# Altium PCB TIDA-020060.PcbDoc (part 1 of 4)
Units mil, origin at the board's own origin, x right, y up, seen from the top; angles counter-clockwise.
Board outline 2114.94 x 3612.21 mil, 4 copper layers (Top Layer, Signal Layer 1, Signal Layer 2, Bottom Layer), stack 61.811 mil thick; 272 components, 167 nets, 840 pads, 352 vias.
Unrouted connection lines stored in the file: 261.
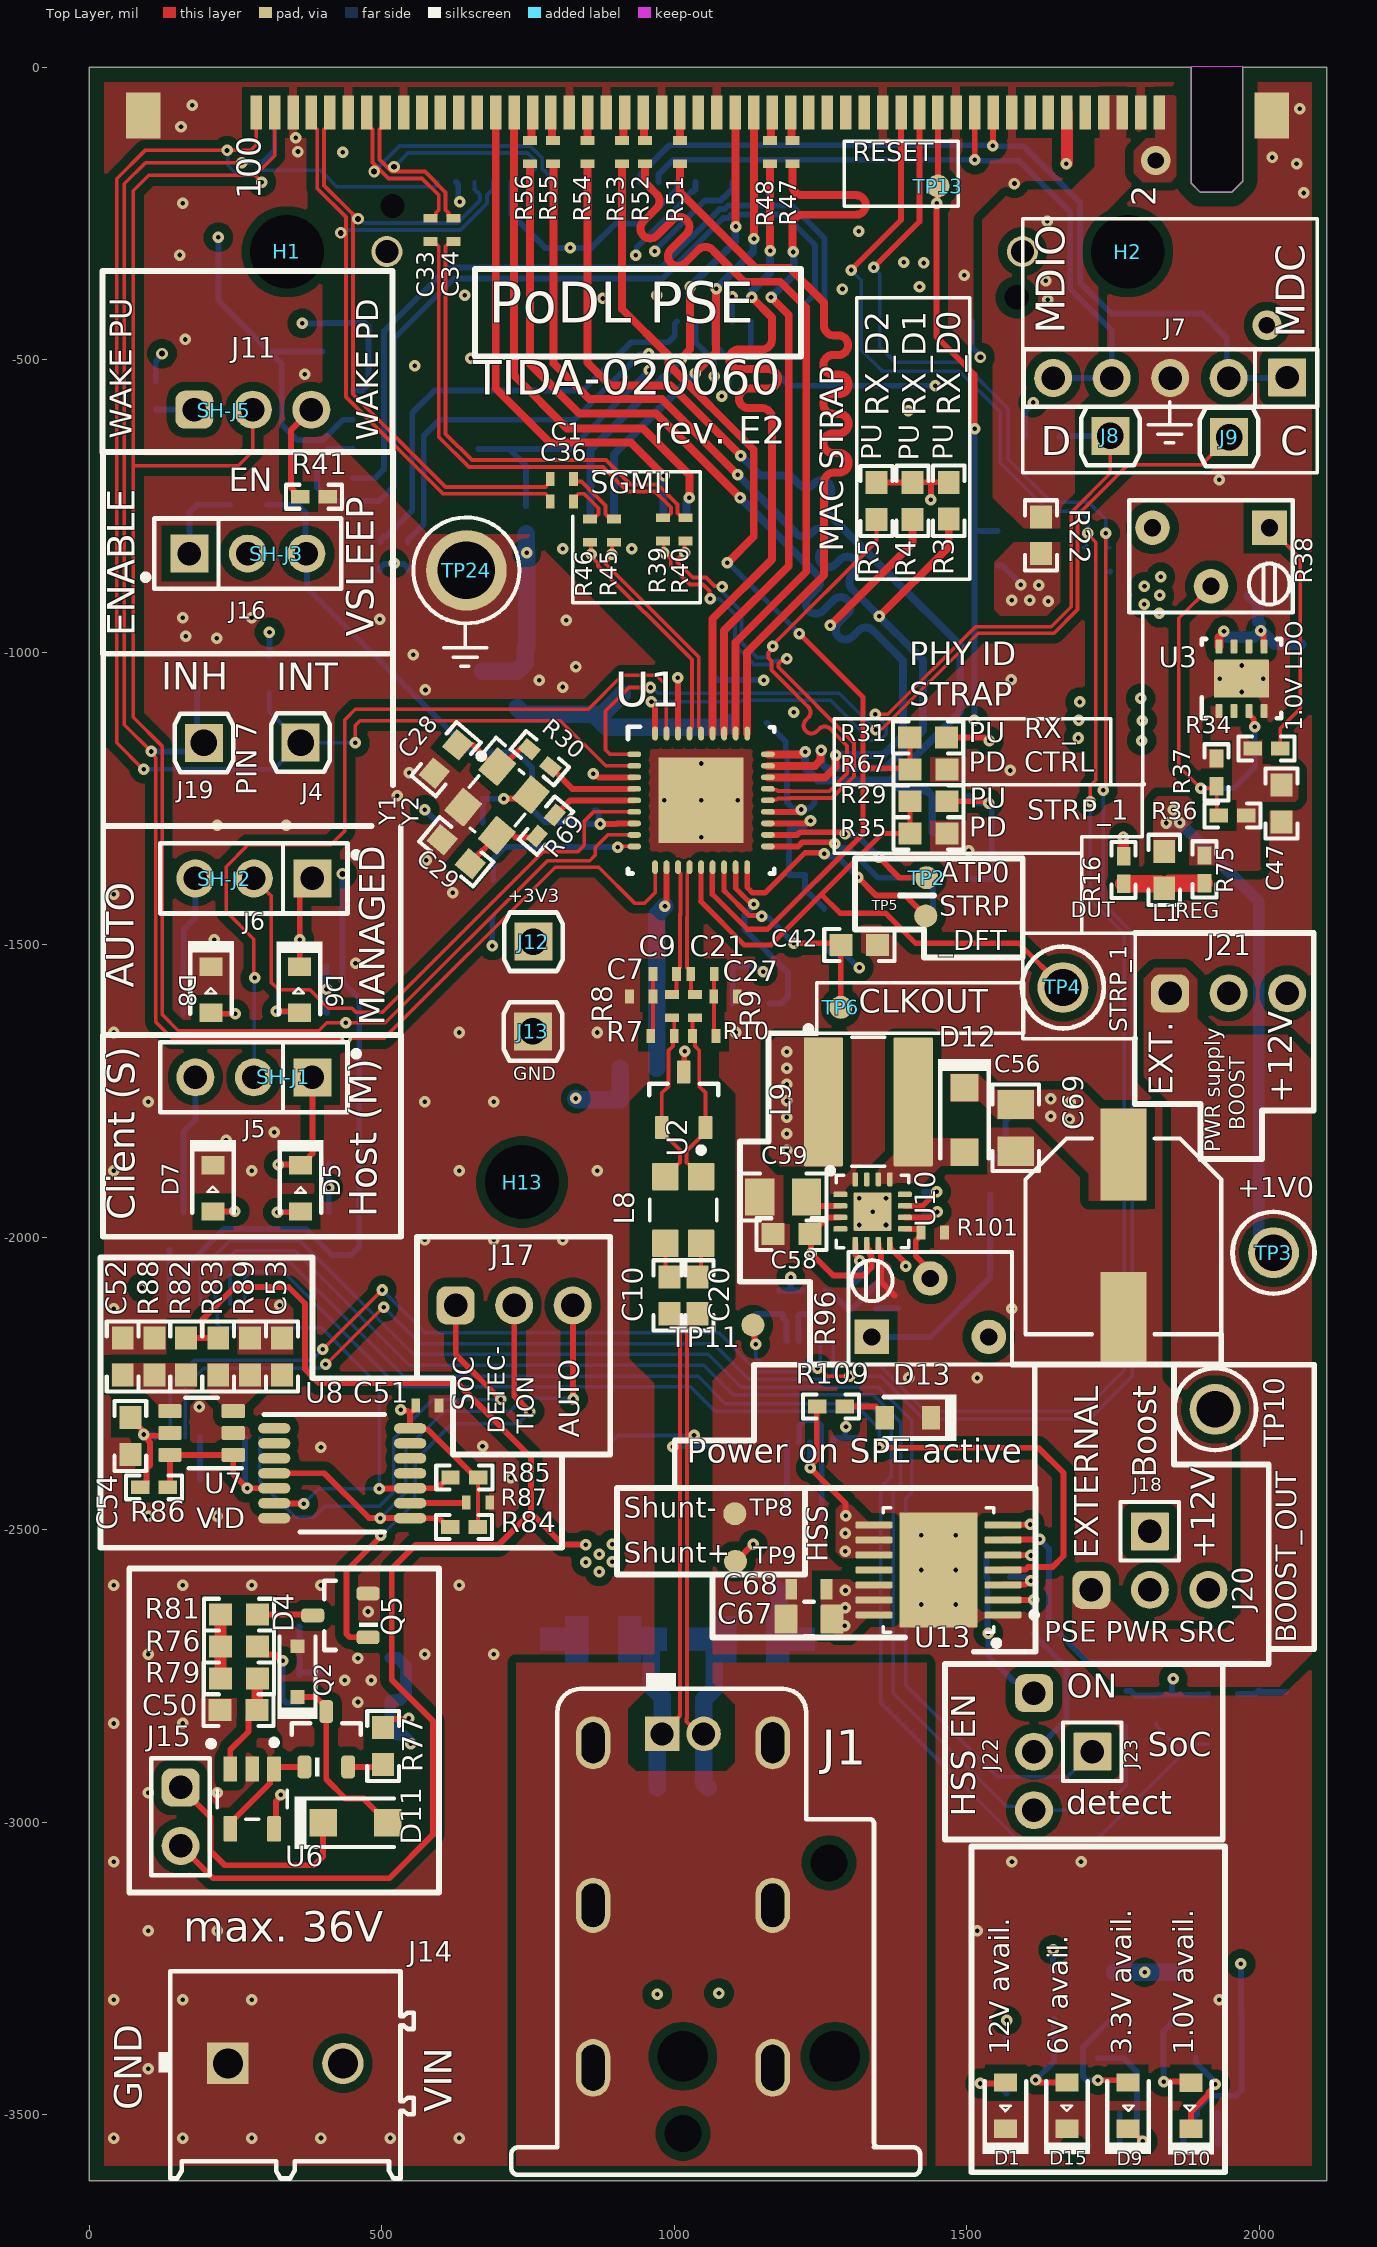
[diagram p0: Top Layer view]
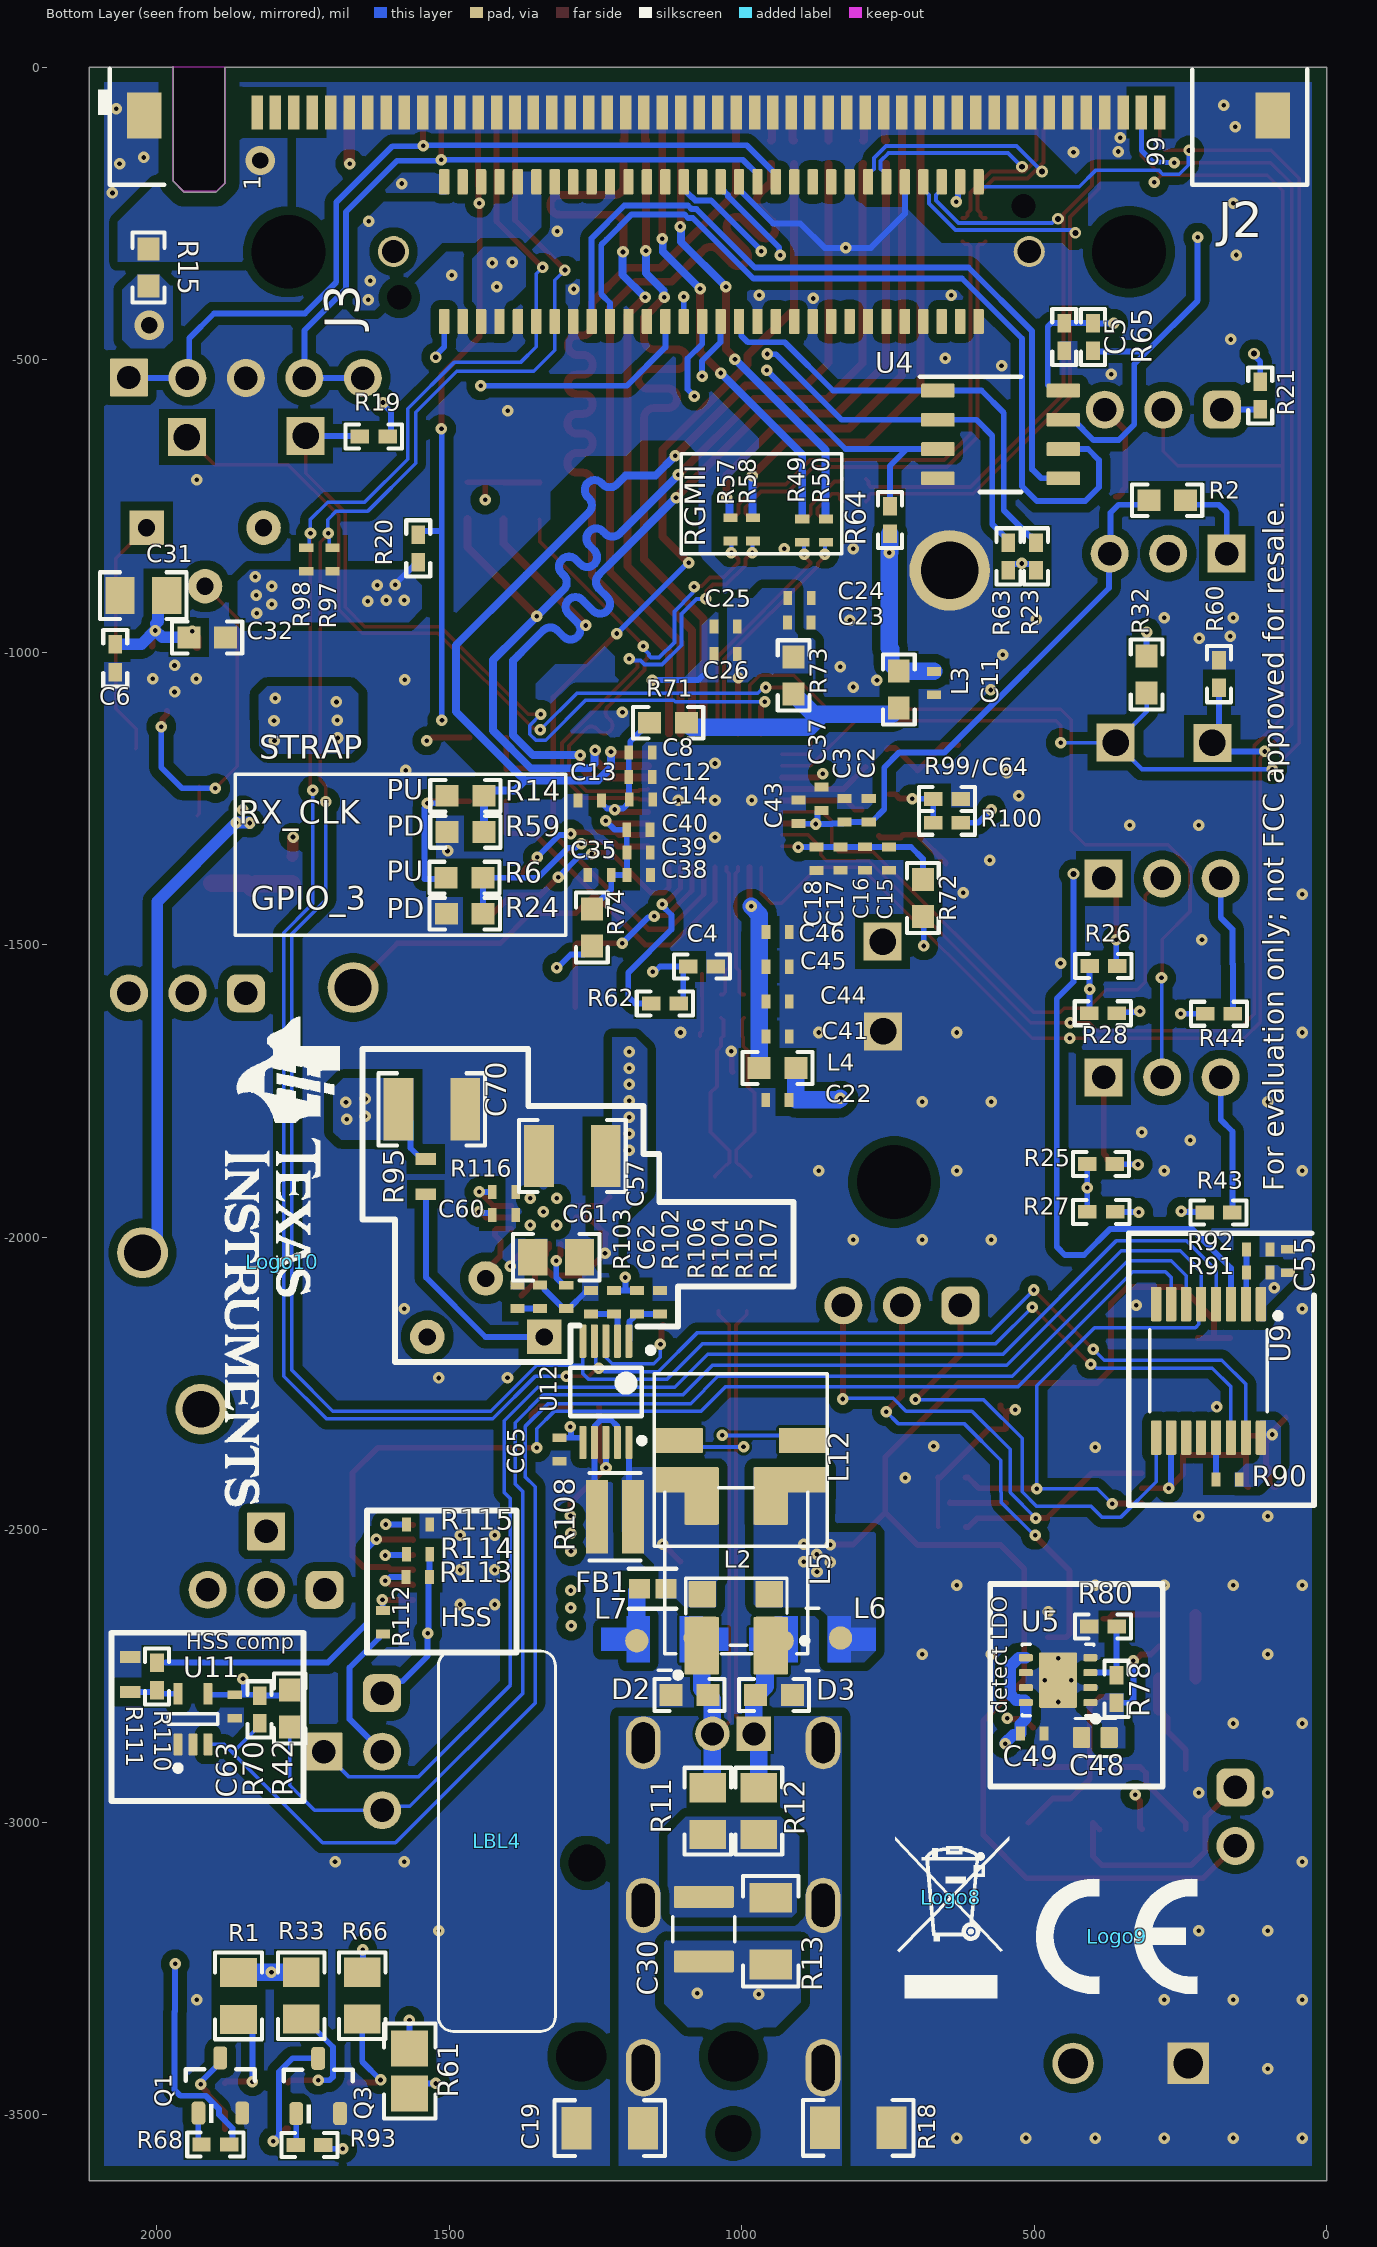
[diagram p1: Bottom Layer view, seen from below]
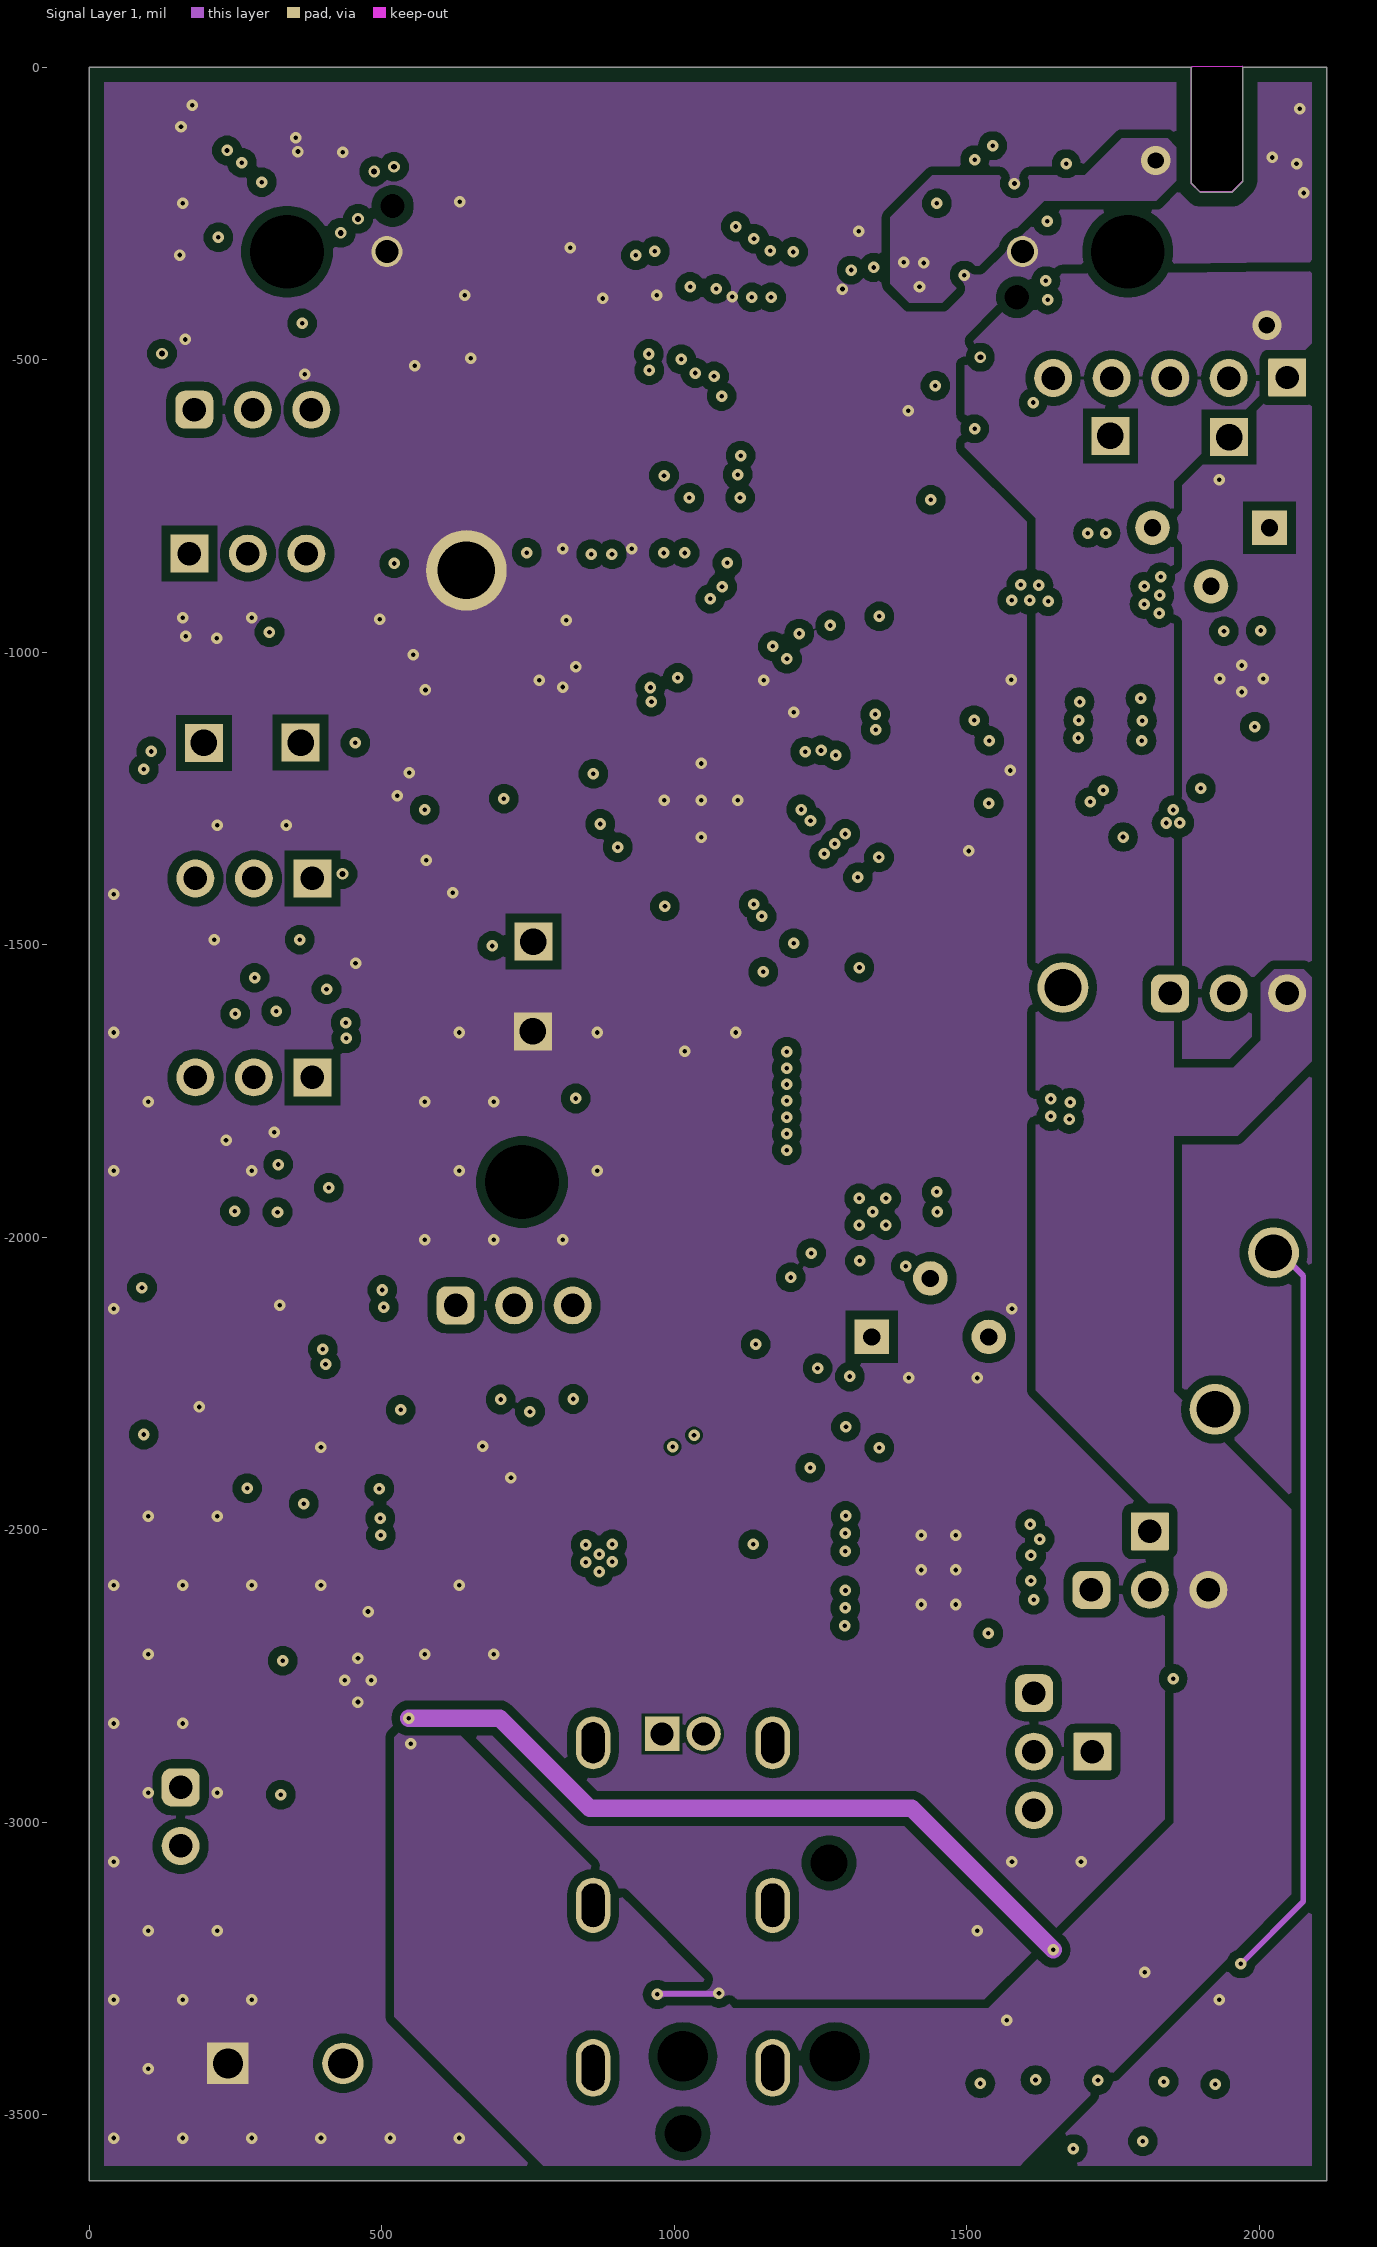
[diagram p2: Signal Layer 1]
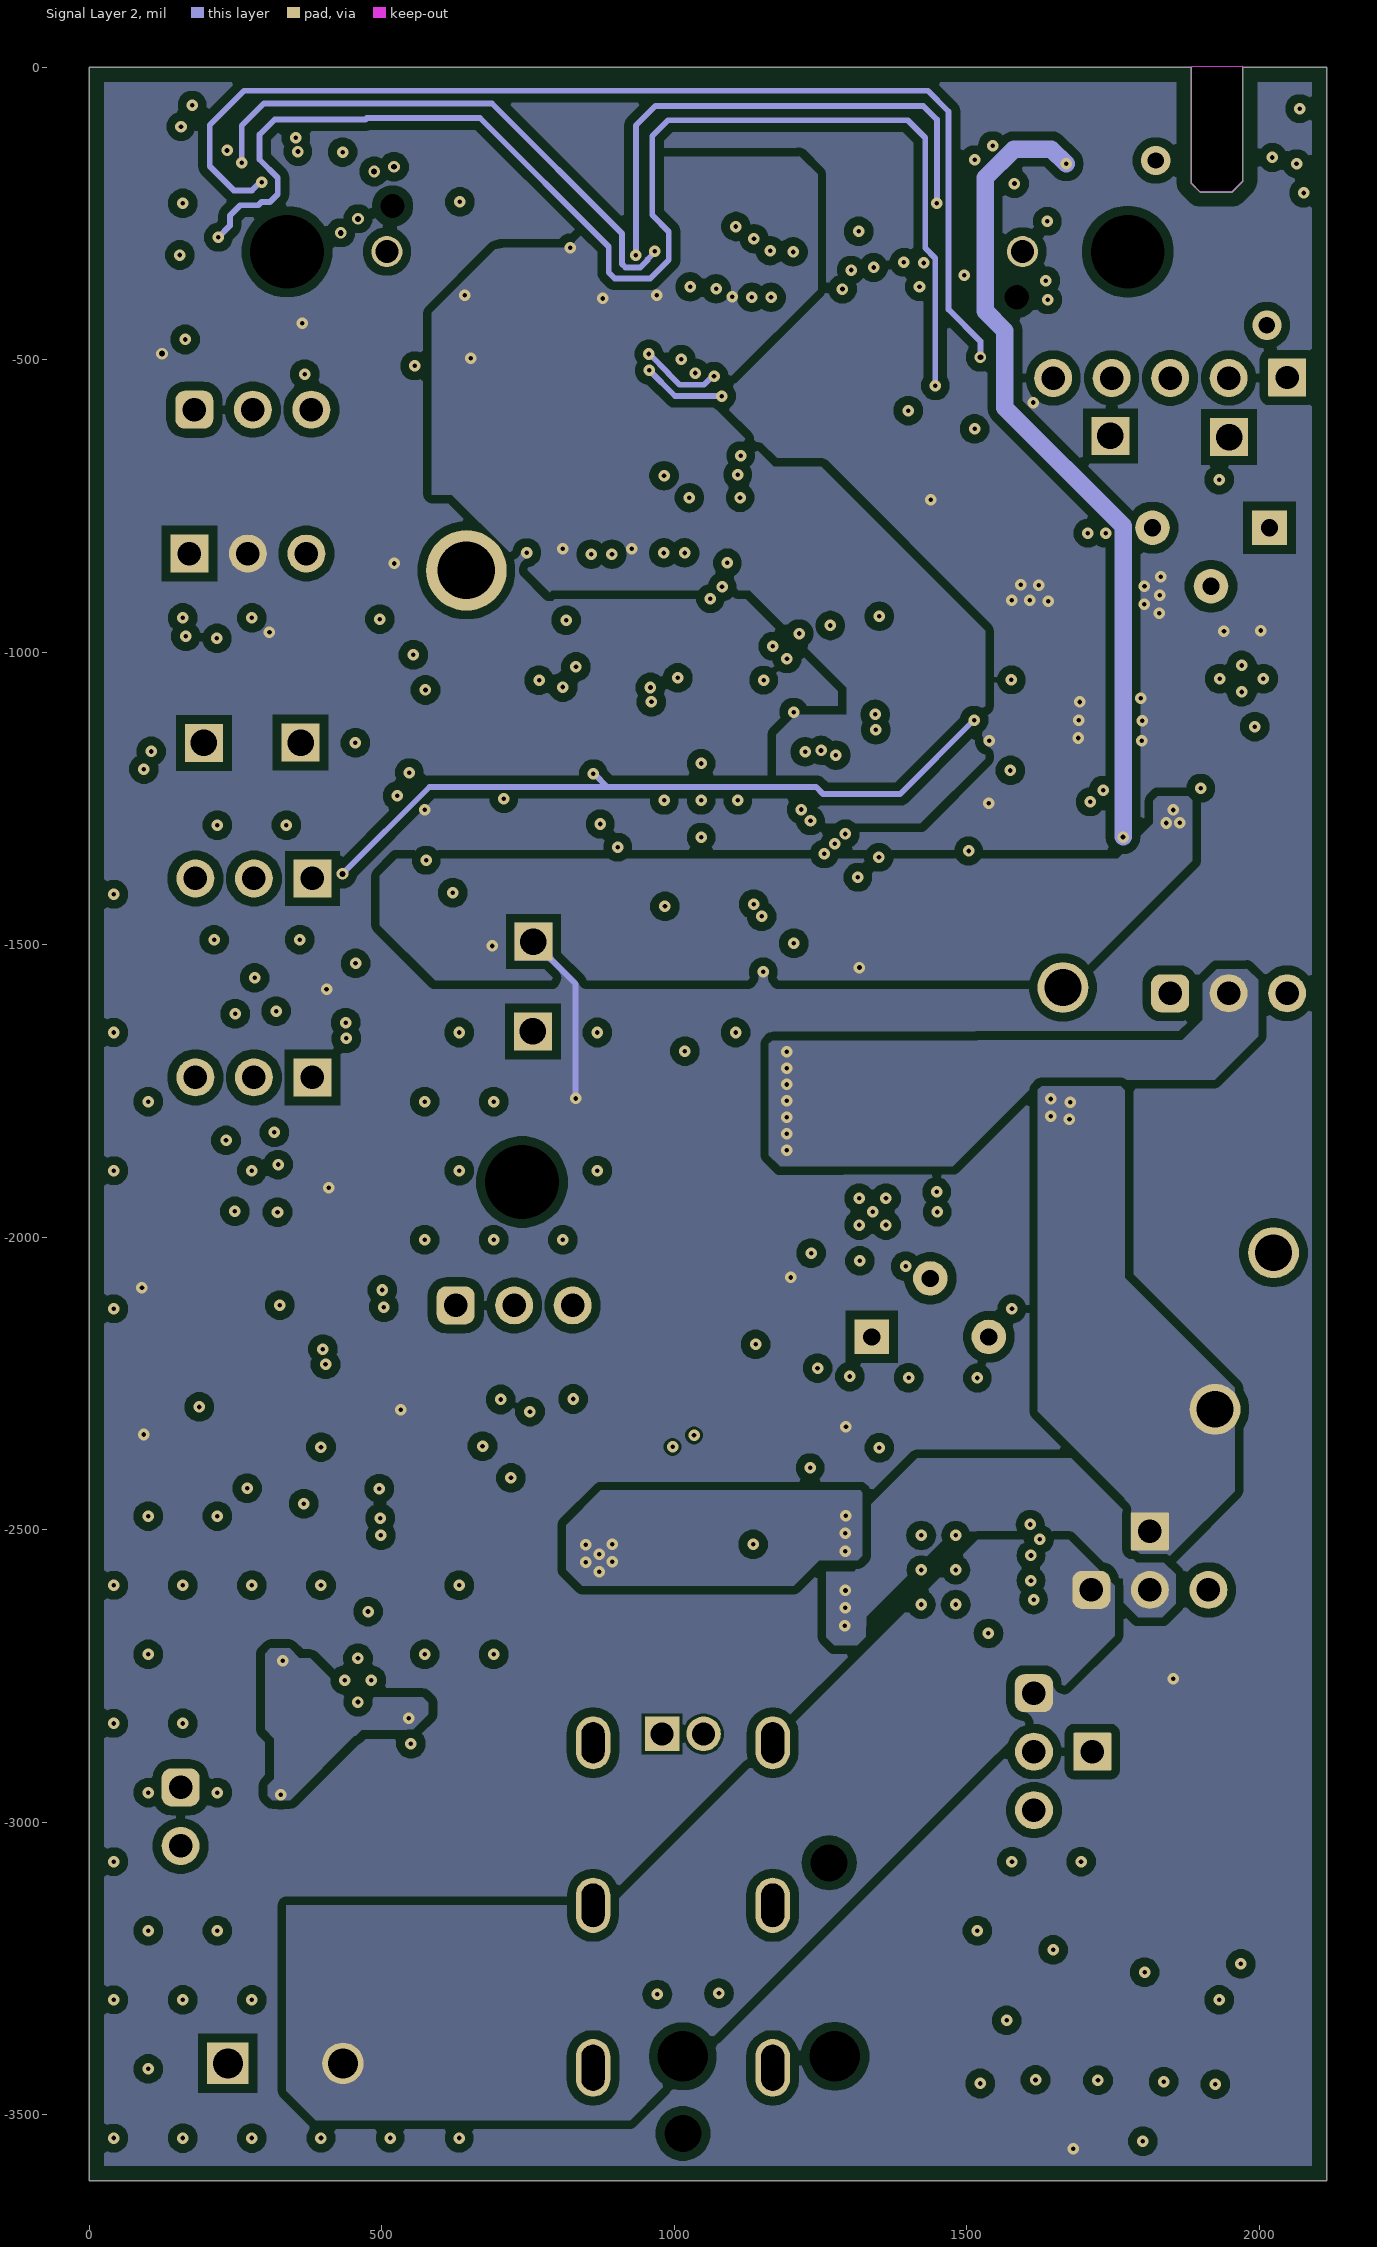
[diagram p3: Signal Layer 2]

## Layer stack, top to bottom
Top Solder: solder mask 0.4, Solder Resist, Dk 3.5
Top Layer: signal copper 1.378
Dielectric1: prepreg 7.874, PP-022, Dk 4.5
Signal Layer 1: signal copper 1.378
Dielectric 2: core 40.5512, Core-042, Dk 4.6
Signal Layer 2: signal copper 1.378
Dielectric 3: prepreg 7.874, PP-022, Dk 4.5
Bottom Layer: signal copper 1.378
Bottom Solder: solder mask 0.4, Solder Resist, Dk 3.5

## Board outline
0,-3612.21 2114.94,-3612.21 2114.94,0 1971.39,0 1971.39,-195 1953.39,-213 1898.64,-213 1883.39,-197.75 1883.39,0 0,0
cut-out: 1884.39,0 1883.39,-1 1883.39,-197.75 1898.64,-213 1953.39,-213 1971.39,-195 1971.39,1

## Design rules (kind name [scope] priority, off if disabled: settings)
AcuteAngle [All] p1: minimum=4.50000000000000E+0001 checktracksonly=FALSE
AssemblyTestPointUsage [All] p1: valid=2
BoardOutlineClearance BoardOutlineClearance_MountingHoles [OnCopper and InComponentClass('Mounting Holes')] p1: gap=35 ignorepadtopadclearanceinfootprint=FALSE
BoardOutlineClearance BoardOutlineClearance_Poly [OnCopper and IsPoly] p2: gap=25 ignorepadtopadclearanceinfootprint=FALSE
BoardOutlineClearance [OnCopper and Not InComponentClass('Logo') and not InComponentClass('FiducialMark') and not InRegion(1000,500,4000,800) and not InPoly] p3: gap=35 ignorepadtopadclearanceinfootprint=FALSE
Clearance Clearance_Keepouts_FID [IsKeepOut and InComponentClass('FiducialMark') vs IsPad and InComponentClass('FiducialMark')] p1: gap=0 ignorepadtopadclearanceinfootprint=FALSE
Clearance Clearance_Keepouts [((IsTrack Or IsArc) And Not InPoly) And IsFree and IsKeepOut vs ((IsTrack Or IsArc) And Not InPoly) And IsFree and IsKeepOut] p2: gap=0 ignorepadtopadclearanceinfootprint=FALSE
Clearance Clearance_Poly_Connectors [InRegionRelative(3345,2820,4790,2995) or InRegionRelative(4870,2815,6285,2995) or InRegionRelative(6370,2790,7785,2995)] p3: gap=5 ignorepadtopadclearanceinfootprint=TRUE except(0: Arc-Hole Track-Hole SMDPad-Hole THPad-Hole Via-Hole Fill-Hole Poly-Hole Region-Hole Text-Hole; 10: Arc-Fill Arc-Poly Arc-Region Track-Fill Track-Poly Track-Region SMDPad-Fill SMDPad-Poly SMDPad-Region THPad-Fill THPad-Poly THPad-Region Via-Fill Via-Poly Via-Region Fill-Fill Fill-Poly Fill-Region Poly-Poly Poly-Region Region-Region)
Clearance Clearance_Poly_100OHM [InNetClass('100 OHM')] p4: gap=5 ignorepadtopadclearanceinfootprint=TRUE except(0: Arc-Hole Track-Hole SMDPad-Hole THPad-Hole Via-Hole Fill-Hole Poly-Hole Region-Hole Text-Hole)
Clearance "Clearance_Poly_50OHM_Outer Layers" [InNetClass('50 Ohm') vs OnLayer('Top Layer') or OnBottomLayer] p5: gap=5 ignorepadtopadclearanceinfootprint=TRUE except(0: Arc-Hole Track-Hole SMDPad-Hole THPad-Hole Via-Hole Fill-Hole Poly-Hole Region-Hole Text-Hole; 15: Fill-Fill Fill-Poly Fill-Region Poly-Poly Poly-Region Region-Region; 27: Arc-Fill Arc-Poly Arc-Region Track-Fill Track-Poly Track-Region SMDPad-Fill SMDPad-Poly SMDPad-Region THPad-Fill THPad-Poly THPad-Region Via-Fill Via-Poly Via-Region)
Clearance "Clearance_Poly_50OHM_Inner Layers" [InNetClass('50 Ohm')] p6: gap=5 ignorepadtopadclearanceinfootprint=FALSE except(0: Arc-Hole Track-Hole SMDPad-Hole THPad-Hole Via-Hole Fill-Hole Poly-Hole Region-Hole Text-Hole; 15: Fill-Fill Fill-Poly Fill-Region Poly-Poly Poly-Region Region-Region; 22.5: Arc-Fill Arc-Poly Arc-Region Track-Fill Track-Poly Track-Region SMDPad-Fill SMDPad-Poly SMDPad-Region THPad-Fill THPad-Poly THPad-Region Via-Fill Via-Poly Via-Region)
Clearance Clearance_720Gnd [InNet('720_GND') vs InNet('NetC66_1')] p7: gap=15 ignorepadtopadclearanceinfootprint=FALSE except(0: Arc-Hole Track-Hole SMDPad-Hole THPad-Hole Via-Hole Fill-Hole Poly-Hole Region-Hole Text-Hole; 45: Fill-Fill Fill-Poly Fill-Region Poly-Poly Poly-Region Region-Region)
Clearance Clearance_867GND [InNet('867_GND') vs InNet('PHY1_EARTH')] p8: gap=15 ignorepadtopadclearanceinfootprint=FALSE except(0: Arc-Hole Track-Hole SMDPad-Hole THPad-Hole Via-Hole Fill-Hole Poly-Hole Region-Hole Text-Hole; 7.79: Arc-Arc Arc-Track Track-Track; 45: Fill-Fill Fill-Poly Fill-Region Poly-Poly Poly-Region Region-Region)
Clearance Clearance_822GND [InNet('822_GND') vs InNet('ETH1_EARTH')] p9: gap=15 ignorepadtopadclearanceinfootprint=FALSE except(0: Arc-Hole Track-Hole SMDPad-Hole THPad-Hole Via-Hole Fill-Hole Poly-Hole Region-Hole Text-Hole; 45: Fill-Fill Fill-Poly Fill-Region Poly-Poly Poly-Region Region-Region)
Clearance Clearance_Poly [InPolygon] p10: gap=15 ignorepadtopadclearanceinfootprint=FALSE except(0: Arc-Hole Track-Hole SMDPad-Hole THPad-Hole Via-Hole Fill-Hole Poly-Hole Region-Hole Text-Hole)
Clearance Clearance_FiducialMark [IsKeepOut and InComponentClass('FiducialMark') vs IsPad and InComponentClass('FiducialMark')] p11: gap=0 ignorepadtopadclearanceinfootprint=FALSE
Clearance Clearance_Keepouts_J6 [IsKeepOut and InComponent('J6') vs IsPad and InComponent('J6')] p12: gap=0 ignorepadtopadclearanceinfootprint=FALSE
Clearance [All] p13: gap=5 ignorepadtopadclearanceinfootprint=TRUE except(0: Arc-Hole Track-Hole SMDPad-Hole THPad-Hole Via-Hole Fill-Hole Poly-Hole Region-Hole Text-Hole)
ComponentClearance ComponentClearance_MountingHoles_FiducialMarks [InComponentClass('Mounting Holes') vs InComponentClass('FiducialMark')] p1: gap=20 collisioncheckmode=3 verticalgap=10 showdistances=FALSE
ComponentClearance ComponentClearance_Shunt [InComponentClass('Header') vs InComponentClass('Shunt')] p2: gap=0 collisioncheckmode=3 verticalgap=0 showdistances=FALSE
ComponentClearance ComponentClearance_Logo [InComponentClass('Logo')] p3: gap=20 collisioncheckmode=3 verticalgap=10 showdistances=FALSE
ComponentClearance ComponentClearance_ScrewToNut [(HasFootprint('NY PMS 440 0025 PH')) vs (HasFootprint('Keystone_1902C'))] p4: gap=5 collisioncheckmode=3 verticalgap=10 showdistances=FALSE
ComponentClearance ComponentClearance_MountingHoles [InComponentClass('Mounting Holes')] p5: gap=70 collisioncheckmode=3 verticalgap=0 showdistances=FALSE
ComponentClearance ComponentClearance_SmallPassives [HasFootprint('0201*') or HasFootprint('0402*') or HasFootprint('0508') or HasFootprint('0603*') or HasFootprint('0612') or HasFootprint('0805*') or HasFootprint('0815*') or HasFootprint('0830*') or HasFootprint('1206*') or HasFootprint('1210*') or HasFootprint('1808*') or HasFootprint('1812*') or HasFootprint('1825*') or HasFootprint('2010*') or HasFootprint('2220*') or HasFootprint('2225*') or HasFootprint('2512*') or HasFootprint('2728*') or HasFootprint('3518*') vs HasFootprint('0201*') or HasFootprint('0402*') or HasFootprint('0508') or HasFootprint('0603*') or HasFootprint('0612') or HasFootprint('0805*') or HasFootprint('0815*') or HasFootprint('0830*') or HasFootprint('1206*') or HasFootprint('1210*') or HasFootprint('1808*') or HasFootprint('1812*') or HasFootprint('1825*') or HasFootprint('2010*') or HasFootprint('2220*') or HasFootprint('2225*') or HasFootprint('2512*') or HasFootprint('2728*') or HasFootprint('3518*')] p6: gap=15 collisioncheckmode=3 verticalgap=10 showdistances=FALSE
ComponentClearance ComponentClearance_THtoSMT [IsThruComponent vs IsSMTComponent] p7: gap=1 collisioncheckmode=3 verticalgap=1 showdistances=FALSE
ComponentClearance ComponentClearance_THtoTH [IsThruComponent vs IsThruComponent] p8: gap=20 collisioncheckmode=3 verticalgap=30 showdistances=FALSE
ComponentClearance [All] p9: gap=19.68 collisioncheckmode=3 verticalgap=10 showdistances=FALSE
DiffPairsRouting D100 [All] p1: maxlimit=5 minlimit=5 mostfreqgap=5 toplayer_minwidth=6.73 toplayer_maxwidth=6.73 toplayer_prefwidth=6.73 midlayer1_minwidth=2.59 midlayer1_maxwidth=2.59 midlayer1_prefwidth=2.59 midlayer4_minwidth=2.59 midlayer4_maxwidth=2.59 midlayer4_prefwidth=2.59 bottomlayer_minwidth=6.73 bottomlayer_maxwidth=6.73 bottomlayer_prefwidth=6.73 impedanceprofiledriven=TRUE maxuncoupledlength=500
FabricationTestPointUsage TestPointUsage [All] p1: valid=2 allowmultiple=FALSE
FabricationTestpoint Testpoint [All] p1: side=3 testpointundercomponent=TRUE minsize=40 maxsize=100 preferedsize=60 minholesize=0 maxholesize=40 preferedholesize=32 testpointgrid=1 allowsidetop=TRUE allowsidebottom=TRUE usegrid=TRUE gridtolerance=0.01
FanoutControl Fanout_LCC [IsLCC] p1: bgadir=Out bgaviamode=Centered fanoutstyle=Auto fanoutdirection=Alternating viagrid=1 // Fanout_LCC (Default Rule)
FanoutControl Fanout_BGA [IsBGA] p2: bgadir=Out bgaviamode=Centered fanoutstyle=Auto fanoutdirection=Alternating viagrid=1 // Fanout_BGA (Default Rule)
FanoutControl Fanout_Default [All] p4: bgadir=Out bgaviamode=Centered fanoutstyle=Auto fanoutdirection=Alternating viagrid=1 // Fanout_Default (Default Rule)
FanoutControl Fanout_Small [(CompPinCount < 5)] p5: bgadir=Out bgaviamode=Centered fanoutstyle=Auto fanoutdirection=OutThenIn viagrid=1 // Fanout_Small (Default Rule)
Height [All] p1: minheight=0 maxheight=1200 prefheight=500
HoleSize [All] p1: absolutevalues=TRUE maxlimit=251 minlimit=7.87 maxpercent=80.000 minpercent=20.000
Length Length_RXCTRL_T1 [InNet('720_RX_CTRL')] p1: maxlimit=1983.72 minlimit=1839.72
Length Length_RXCTRL_TX [InNet('867_RX_CTRL')] p2: maxlimit=1238.89 minlimit=1234.89
Length Length_RXCTRL_822 [InNet('822_RX_CTRL')] p3: maxlimit=1278.61 minlimit=1274.61
Length Length_RXCLK_T1 [InNet('720_RX_CLK')] p4: maxlimit=1675.3 minlimit=1671.3
Length Length_RXCLK_TX [InNet('867_RX_CLK')] p5: maxlimit=1135.55 minlimit=1131.55
Length Length_RXCLK_822 [InNet('822_RX_CLK')] p6: maxlimit=1263.98 minlimit=1259.98
Length Length_RXD3_T1 [InNet('720_RX_D3')] p7: maxlimit=1781 minlimit=1781
Length Length_RXD3_TX [InNet('867_RX_D3')] p8: maxlimit=1068.43 minlimit=1064.43
Length Length_RXD3_822 [InNet('822_RX_D3')] p9: maxlimit=1238.82 minlimit=1238.82
Length Length_RXD2_T1 [InNet('720_RX_D2')] p10: maxlimit=1767.58 minlimit=1763.58
Length Length_RXD2_TX [InNet('867_RX_D2')] p11: maxlimit=1103.7 minlimit=1099.7
Length Length_RXD2_822 [InNet('822_RX_D2')] p12: maxlimit=1263.98 minlimit=1259.98
Length Length_RXD1_T1 [InNet('720_RX_D1')] p13: maxlimit=1740.99 minlimit=1736.99
Length Length_RXD1_TX [InNet('867_RX_D1')] p14: maxlimit=1116.26 minlimit=1112.26
Length Length_RXD1_822 [InNet('822_RX_D1')] p15: maxlimit=1278.61 minlimit=1274.61
Length Length_RXD0_T1 [InNet('720_RX_D0')] p16: maxlimit=1687.77 minlimit=1683.77
Length Length_RXD0_TX [InNet('867_RX_D0')] p17: maxlimit=1128.82 minlimit=1124.82
Length Length_RXD0_822 [InNet('822_RX_D0')] p18: maxlimit=1291.56 minlimit=1287.56
Length Length_TXCTRL_T1 [InNet('720_TX_CTRL')] p19: maxlimit=1365.97 minlimit=1361.97
Length Length_TXCTRL_TX [InNet('867_TX_CTRL')] p20: maxlimit=1356.54 minlimit=1356.53
Length Length_TXCTRL_822 [InNet('822_TX_CTRL')] p21: maxlimit=2134.19 minlimit=2130.19
Length Length_TXCLK_T1 [InNet('720_TX_CLK')] p22: maxlimit=1351 minlimit=1350.99
Length Length_TXCLK_TX [InNet('867_TX_CLK')] p23: maxlimit=1294.95 minlimit=1290.95
Length Length_TXCLK_822 [InNet('822_TX_CLK')] p24: maxlimit=2121.63 minlimit=2117.63
Length Length_TXD3_T1 [InNet('720_TX_D3')] p25: maxlimit=1378.94 minlimit=1374.94
Length Length_TXD3_TX [InNet('867_TX_D3')] p26: maxlimit=1237.07 minlimit=1233.07
Length Length_TXD3_822 [InNet('822_TX_D3')] p27: maxlimit=2107.07 minlimit=2107.07
Length Length_TXD2_T1 [InNet('720_TX_D2')] p28: maxlimit=1392.73 minlimit=1388.73
Length Length_TXD2_TX [InNet('867_TX_D2')] p29: maxlimit=1258.76 minlimit=1254.76
Length Length_TXD2_822 [InNet('822_TX_D2')] p30: maxlimit=2121.63 minlimit=2117.63
Length Length_TXD1_T1 [InNet('720_RX_D1')] p31: maxlimit=1380.86 minlimit=1376.86
Length Length_TXD1_TX [InNet('867_TX_D1')] p32: maxlimit=1271.52 minlimit=1267.52
Length Length_TXD1_822 [InNet('822_TX_D1')] p33: maxlimit=2134.19 minlimit=2130.19
Length Length_TXD0_T1 [InNet('720_TX_D0')] p34: maxlimit=1367.88 minlimit=1363.88
Length Length_TXD0_TX [InNet('867_TX_D0')] p35: maxlimit=1284.08 minlimit=1280.08
Length Length_TXD0_822 [InNet('822_TX_D0')] p36: maxlimit=2146.74 minlimit=2142.74
Length Length_MDC_T1 [InNet('720_MDC')] p37: maxlimit=1237.86 minlimit=1233.86
Length Length_MDC_TX [InNet('867_MDC')] p38: maxlimit=1656.95 minlimit=1652.95
Length Length_MDC_822 [InNet('822_MDC')] p39: maxlimit=2111.7 minlimit=2107.7
Length Length_MDIO_T1 [InNet('720_MDIO')] p40: maxlimit=1235.86 minlimit=1235.86
Length Length_MDIO_TX [InNet('867_MDIO')] p41: maxlimit=1654.96 minlimit=1654.94
Length Length_MDIO_822 [InNet('822_MDIO')] p42: maxlimit=2109.71 minlimit=2109.7
Length Length_RXDV_MainBoard [InNet('RXDV')] p43: maxlimit=2757.36 minlimit=2753.36
Length Length_TXEN_MainBoard [InNet('TXEN_RGMII_TD3')] p44: maxlimit=1989.84 minlimit=1985.84
Length Length_RXCLK_MainBoard [InNet('RXCLK')] p45: maxlimit=2788.45 minlimit=2784.45
Length Length_TXCLK_MainBoard [InNet('TXCLK_RGMII_TXC')] p46: maxlimit=1820.98 minlimit=1820.97
Length Length_RXD3_MainBoard [InNet('RXD3')] p47: maxlimit=2578.2 minlimit=2578.18
Length Length_TXD3_MainBoard [InNet('TXD3_RGMII_TD2')] p48: maxlimit=1936.35 minlimit=1932.35
Length Length_RXD2_MainBoard [InNet('RXD2')] p49: maxlimit=2801.48 minlimit=2797.48
Length Length_TXD2_MainBoard [InNet('TXD2_RGMII_TD1')] p50: maxlimit=1929.81 minlimit=1925.81
Length Length_RXD1_MainBoard [InNet('RXD1')] p51: maxlimit=2894.13 minlimit=2890.13
Length Length_TXD1_MainBoard [InNet('TXD1_RGMII_TD0')] p52: maxlimit=2004.59 minlimit=2000.59
Length Length_RXD0_MainBoard [InNet('RXD0')] p53: maxlimit=2716.98 minlimit=2712.98
Length Length_TXD0_MainBoard [InNet('TXD0_RGMII_TXCTL')] p54: maxlimit=2014.26 minlimit=2010.26
MatchedLengths SGMII_TX_1 [InxSignalClass('SGMII_TX')] p1: tolerance=2 checknetsindiffpair=FALSE checkdiffpairvsdiffpair=TRUE checkxsignals=TRUE checkothers=TRUE
MatchedLengths SGMII_TX_cap [InxSignalClass('SGMII_TX_cap')] p2: tolerance=2 checknetsindiffpair=FALSE checkdiffpairvsdiffpair=TRUE checkxsignals=TRUE checkothers=TRUE
MatchedLengths RGMII_TX [InxSignalClass('RGMII_TX')] p3: tolerance=10 checknetsindiffpair=FALSE checkdiffpairvsdiffpair=TRUE checkxsignals=TRUE checkothers=TRUE
MatchedLengths RGMII_RX [InxSignalClass('RGMII_RX')] p4: tolerance=10 checknetsindiffpair=FALSE checkdiffpairvsdiffpair=TRUE checkxsignals=TRUE checkothers=TRUE
MatchedLengths SGMII_RX [InxSignalClass('SGMII_RX')] p5: tolerance=5 checknetsindiffpair=TRUE checkdiffpairvsdiffpair=FALSE checkxsignals=FALSE checkothers=FALSE
MatchedLengths SGMII_TX [InxSignalClass('SGMII_TX')] p6: tolerance=5 checknetsindiffpair=TRUE checkdiffpairvsdiffpair=FALSE checkxsignals=FALSE checkothers=FALSE
MaxMinImpedance [All] p1 off: minimum=45.00 maximum=55.00
MinimumAnnularRing MinimumAnnularRing_ThermalPadVias [IsVia and InAnyComponent] p1: minimumring=5.91
MinimumAnnularRing [All] p2: minimumring=5
MinimumSolderMaskSliver MinimumSolderMaskSliver_Logo [InComponentClass('Logo') vs InComponentClass('Logo')] p1: minsoldermaskwidth=0.7
MinimumSolderMaskSliver [All] p2: minsoldermaskwidth=3.7
ParallelSegment [All] p1: limit=10000 gap=8
PlaneConnect [All] p1: planeconnectstyle=Relief reliefexpansion=10 reliefentries=4 reliefconductorwidth=10 reliefairgap=10
PolygonConnect [All] p1: connectstyle=Direct reliefconductorwidth=10 reliefentries=4 polygonreliefangle="90 Angle" airgapwidth=10
RoutingVias ThermalPadVias [IsVia and InAnyComponent] p1: holewidth=7.87 width=19.68 viastyle="Through Hole" minholewidth=7.87 minwidth=19.68 maxholewidth=12.99 maxwidth=23.62
RoutingVias [All] p2: holewidth=10 width=20 viastyle="Through Hole" minholewidth=7.87 minwidth=19 maxholewidth=40 maxwidth=65
SilkToBoardRegionClearance [Not ((IsComment or IsDesignator) And (Hide <> 'False')) and not InRegion(1000,500,4000,800)] p1:
SilkToSilkClearance SilkToSilkClearance_Pb-FreeLogo [(HasFootprint('Pb-Free_Overlay_Medium') OR HasFootprint('Pb-Free_Overlay_Small')) vs (HasFootprint('Pb-Free_Overlay_Medium') OR HasFootprint('Pb-Free_Overlay_Small'))] p1: silktosilkclearance=0
SilkToSilkClearance [All] p2: silktosilkclearance=0
SilkToSolderMaskClearance SilkToComponentPadClearance [(IsPad or IsFill or IsRegion) and InAnycomponent] p1: minsilkscreentomaskgap=3.3 clearancetoexposedcopper=TRUE
SilkToSolderMaskClearance "Silk to Solder Mask Opening" [All] p2: minsilkscreentomaskgap=3.94 clearancetoexposedcopper=FALSE
SolderMaskExpansion [All] p1: expansion=1.97 istentingtop=FALSE
Width RGMII_TX_width [InNetClass('AE_RGMII_TX')] p1: maxlimit=13.51 minlimit=9.05 preferedwidth=13.51 toplayer_minwidth=13.51 midlayer1_maxwidth=9.05 midlayer1_prefwidth=9.05 midlayer4_maxwidth=9.05 midlayer4_prefwidth=9.05 bottomlayer_minwidth=13.51 impedanceprofiledriven=TRUE minimp=50.000000 maximp=50.000000 favimp=50.000000
Width RGMII_RX_width [InNetClass('AE_RGMII_RX')] p2: maxlimit=13.51 minlimit=9.05 preferedwidth=13.51 toplayer_minwidth=13.51 midlayer1_maxwidth=9.05 midlayer1_prefwidth=9.05 midlayer4_maxwidth=9.05 midlayer4_prefwidth=9.05 bottomlayer_minwidth=13.51 impedanceprofiledriven=TRUE minimp=50.000000 maximp=50.000000 favimp=50.000000
Width [All] p3: maxlimit=10 minlimit=10 preferedwidth=10
Width Width_1 [InNetClass('AE_MDI')] p4: maxlimit=9 minlimit=3 preferedwidth=5 toplayer_minwidth=5 midlayer1_maxwidth=6.73 midlayer1_prefwidth=3 midlayer4_maxwidth=6.73 midlayer4_prefwidth=3 bottomlayer_minwidth=5 minimp=50.000000 maximp=50.000000 favimp=50.000000
14 further rules are at their usual default settings.

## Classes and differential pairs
component class HSS: C63 C67 C68 R110 R111 R112 R113 R114 R115 U11 U13
component class GPIO_expander: C55 R90 R91 R92 U9
component class current_sense_sheet: C65 R104 R105 R106 R107 U12
component class Sheet10: C4 C8 C11 C12 C13 C14 C15 C16 C17 C18 C22 C23 C24 C25 C26 C35 C38 C39 C40 C41 C44 C45 C46 L3 L4 R62 R71 R72 R73 R74
component class Sheet9: D1 D9 D10 D15 Q1 Q3 R1 R33 R61 R66 R68 R93
component class Sheet4: C1 C33 C34 C36 R39 R40 R45 R46
component class Sheet3: C5 R23 R63 R64 R65 U4
component class Sheet11: D5 D6 D7 D8 J5 J6 R25 R26 R27 R28 R43 R44 SH-J1 SH-J2
component class Sheet18: C6 C31 C32 C47 L1 R34 R36 R37 R38 R75 TP3 U3
component class LM5158QRTERQ1: C56 C57 C58 C59 C60 C61 C62 C69 C70 D12 L9 R95 R96 R101 R102 R103 R116 U10
component class Detections_sheet: C48 C49 C50 C51 C52 C53 C54 D4 D11 J15 Q2 Q5 R76 R77 R78 R79 R80 R81 R82 R83 R84 R85 R86 R87 R88 R89 U5 U6 U7 U8
component class Sheet7: D13 J14 J17 J18 J20 J21 J22 J23 R108 R109 TP8 TP9 TP10
component class Sheet2: J3
component class Main: J4 J11 J19 R15 R16 R20 R21 R22 R32 R41 R42 R60 R70 R97 R98 SH-J5 TP11
component class Shunt: SH-J1 SH-J2 SH-J3 SH-J5
net class "100 OHM": TRD_2_N TRD_2_P TRD_3_N TRD_3_P TRD_4_N TRD_4_P TRD_N TRD_P
component class Sheet6: C7 C9 C10 C19 C20 C21 C27 C30 D2 D3 FB1 J1 L2 L5 L6 L7 L8 L12 R7 R8 R9 R10 R11 R12 R13 R18 U2
net class AE_RGMII_TX: AE_TX_CLK AE_TX_CTRL AE_TX_D2 AE_TX_D3 AE_TX_N AE_TX_P RGMII_TX0 RGMII_TX1 RGMII_TX2 RGMII_TX3 RGMII_TX_CLK RGMII_TX_CTRL
net class AE_RGMII_RX: AE_RX_CLK AE_RX_CTRL AE_RX_D0 AE_RX_D1 AE_RX_N AE_RX_P RGMII_RX0 RGMII_RX1 RGMII_RX2 RGMII_RX3 RGMII_RX_CLK RGMII_RX_CTRL RGMII_TX_CTRL
component class Sheet1: J2 J12 J13 R47 R48 R49 R50 R51 R52 R53 R54 R55 R56 R57 R58 TP24
component class Sheet5: C2 C3 C28 C29 C37 C42 C43 C64 J7 J8 J9 J16 R2 R3 R4 R5 R6 R14 R19 R24 R29 R30 R31 R35 R59 R67 R69 R99 R100 RESET(TP) SH-J3 TP2 TP4 TP5 TP6 TP13 U1 Y1 Y2
component class Header: J4 J5 J6 J7 J8 J9 J11 J12 J13 J15 J16 J17 J18 J19 J20 J21 J22 J23
component class "Mounting Holes": H1 H2 H13
component class Logo: Logo10
component class Sheet8: H1 H2 H13 LBL4 Logo8 Logo9 Logo10 Logo11
component class Label: LBL4
differential pair SGMII_1_TX: +SGMII_1_TX_P -SGMII_1_TX_N
differential pair SGMII_1_RX: +SGMII_1_RX_P -SGMII_1_RX_N
differential pair SGMII_2_TX: +SGMII_2_TX_P -SGMII_2_TX_N
differential pair SGMII_2_RX: +SGMII_2_RX_P -SGMII_2_RX_N
differential pair TRD: +TRD_P -TRD_N
differential pair TRD_4: +TRD_4_P -TRD_4_N
differential pair TRD_3: +TRD_3_P -TRD_3_N
differential pair TRD_2: +TRD_2_P -TRD_2_N
differential pair AE_TX: +AE_TX_P -AE_TX_N
differential pair AE_RX: +AE_RX_P -AE_RX_N

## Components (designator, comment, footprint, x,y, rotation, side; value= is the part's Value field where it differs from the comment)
C1 "C1005X5R1H104K050BB" 0402S 807.58,-703.53 r0 top value=0.1uF
C2 "GRM155R61A106ME11D" 0402S 782.73,-1269.88 r90 bottom value=10uF
C3 "GRT155C71A105KE13D" 0402S 824.02,-1269.88 r90 bottom value=1uF
C4 "GRM155R71E473KA88D" 0402 1067.74,-1536.8 r180 bottom value=0.047uF
C5 "C1005X5R1H104K050BB" 0402 448.63,-460.68 r90 bottom value=0.1uF
C6 "GRT155C71A105KE13D" 0402 2070.81,-1009.98 r270 bottom value=1uF
C7 "GRM1555C1H470FA01D" 0402S 943.44,-1588.23 r0 top value=47pF
C8 "GRM155R61A106ME11D" 0402S 1172.82,-1171.23 r180 bottom value=10uF
C9 "GRM1555C1H220FA01D" 0402S 983.48,-1549.41 r0 top value=22pF
C10 "CGA3E3X7S2A104K080AB" 0603 991.3,-2098.95 r90 top value=0.1uF
C11 "GRM155R61A106ME11D" 0402S 671.45,-1052.46 r270 bottom value=10uF
C12 "GRT155C71A105KE13D" 0402S 1172.98,-1212.57 r180 bottom value=1uF
C13 "C0402C104K4RACAUTO" 0402S 1259.73,-1252.79 r0 bottom value=0.1uF
C14 "GRM155R71E103KA01D" 0402S 1172.14,-1251.75 r0 bottom value=0.01uF
C15 "GRM155R61A106ME11D" 0402S 747.99,-1352.48 r270 bottom value=10uF
C16 "GRT155C71A105KE13D" 0402S 788.9,-1352.22 r270 bottom value=1uF
C17 "C0402C104K4RACAUTO" 0402S 830.8,-1352.45 r270 bottom value=0.1uF
C18 "GRM155R71E103KA01D" 0402S 871.94,-1352.55 r90 bottom value=0.01uF
C19 "GRM31BR73A102KW01L" 1206#1 1225.5,-3522.57 r180 top value=1000pF
C20 "CGA3E3X7S2A104K080AB" 0603 1039.72,-2098.95 r90 top value=0.1uF
C21 "GRM1555C1H220FA01D" 0402S 1048.06,-1549.41 r0 top value=22pF
C22 "GRM155R61A106ME11D" 0402S 938.85,-1765.02 r0 bottom value=10uF
C23 "GRM155R61A106ME11D" 0402S 901.45,-948.66 r180 bottom value=10uF
C24 "GRT155C71A105KE13D" 0402S 901.06,-907.19 r180 bottom value=1uF
C25 "C0402C104K4RACAUTO" 0402S 1027.5,-955.84 r0 bottom value=0.1uF
C26 "GRM155R71E103KA01D" 0402S 1027.5,-1002.85 r180 bottom value=0.01uF
C27 "GRM1555C1H470FA01D" 0402S 1087.35,-1588.37 r0 top value=47pF
C28 "CGA3E2C0G1H220J080AA" 0603 609.65,-1182.36 r230 top value=22pF
C29 "CGA3E2C0G1H220J080AA" 0603 627.11,-1340.71 r140 top value=22pF
C30 "C1210C472KGRAC7800" FP-C1210C472KGRAC7800_1210-MFG 1064.61,-3182.48 r90 bottom value=4.7nF
C31 "GRM21BC71E106KE11L" 0805_HV 2022.84,-902.92 r180 bottom value=10uF
C32 "C1608X7S1A475K080AC" 0603 1913.58,-974.44 r0 bottom value=4.7uF
C33 "C1005X5R1H104K050BB" 0402S 583.4,-277.74 r270 top value=0.1uF
C34 "C1005X5R1H104K050BB" 0402S 622.58,-277.74 r270 top value=0.1uF
C35 "GRM155R61A106ME11D" 0402S 1242.96,-1380.14 r0 bottom value=10uF
C36 "C1005X5R1H104K050BB" 0402S 807.58,-742.32 r0 top value=0.1uF
C37 "C0402C104K4RACAUTO" 0402S 863.34,-1250.2 r90 bottom value=0.1uF
C38 "GRT155C71A105KE13D" 0402S 1175.94,-1380.38 r180 bottom value=1uF
C39 "C0402C104K4RACAUTO" 0402S 1176.06,-1341.72 r180 bottom value=0.1uF
C40 "GRM155R71E103KA01D" 0402S 1176.59,-1303.13 r0 bottom value=0.01uF
C41 "GRM155R61A106ME11D" 0402S 938.55,-1656.56 r180 bottom value=10uF
C42 "GCM188R72A103KA37J" 0603 1316.05,-1500.19 r0 top value=0.01uF
C43 "GRM155R71E103KA01D" 0402S 902.46,-1272.31 r270 bottom value=0.01uF
C44 "GRT155C71A105KE13D" 0402S 938.55,-1596.92 r180 bottom value=1uF
C45 "C0402C104K4RACAUTO" 0402S 938.55,-1537.28 r180 bottom value=0.1uF
C46 "GRM155R71E103KA01D" 0402S 938.55,-1477.58 r0 bottom value=0.01uF
C47 "CL10B106MQ8NRNC" 0603 2037.61,-1258.35 r270 top value=10uF
C48 "C0603C225M8PAC7867" FP-C0603C225M8PAC7867_0603-MFG 395.35,-2854.8 r180 bottom value=2.2µF
C49 "GRM155R61C105MA12D" 0402S 503.4,-2847.86 r180 bottom value=1uF
C50 "885012206040" 0603 254.99,-2807.96 r180 top value=0.01uF
C51 "C0402C104K4RACAUTO" 0402S 577.71,-2286.97 r0 top value=0.1uF
C52 "CGA3E2X7R1H683K080AA" 0603 56.95,-2203.48 r90 top value=0.068uF
C53 "GRM188R71E154KA01D" 0603 329.45,-2203.48 r90 top value=0.15uF
C54 "885012206071" 0603 69.97,-2339.26 r90 top value=0.1uF
C55 "C1005X5R1H104K050BB" 0402S 66.49,-2040.37 r270 bottom value=0.1uF
C56 "C2012X7R2A104K125AA" 0805_HV 1583.39,-1812.59 r270 top value=0.1uF
C57 "GRM32DC72A475KE01L" 1210_220 1289.36,-1860.72 r0 bottom value=4.7uF
C58 "GRM188R72A104KA35D" 0603 1200.11,-1994.4 r180 top value=0.1uF
C59 "CGA4J3X7S2A105K125AB" 0805_HV 1185.97,-1930.98 r180 top value=1uF
C60 "GRM155R71C683KA88D" 0402S 1406.24,-1961.95 r180 bottom value=0.068uF
C61 "C0805C100J5GACTU" 0805_HV 1317.16,-2033.81 r180 bottom value=10pF
C62 "CGA2B2X8R1H102K050BA" 0402S 1344.38,-2101.44 r90 bottom value=1000pF
C63 "C0402C104K4RACAUTO" 0402S 1866.49,-2801.7 r270 bottom value=0.1uF
C64 "C1005X5R1H104K050BB" 0402 648.83,-1250.29 r0 bottom value=0.1uF
C65 "C0402C104K4RACAUTO" 0402S 1311.46,-2362.41 r270 bottom value=0.1uF
C67 "GRM21AR72A224KAC5L" 0805_HV1 1230.17,-2652.41 r180 top value=0.22uF
C68 "GRM188R72A104KA35D" 0603S 1229.87,-2601.48 r180 top value=0.1uF
C69 "EEE-FK2A220P" SM_RADIAL_F 1767.38,-1998.16 r270 top value=22uF
C70 "GRM32DC72A475KE01L" 1210_220 1529.61,-1781.01 r180 bottom value=4.7uF
D1 "LG M67K-G1J2-24-Z" LG_M67K_Green 1566.18,-3483.92 r90 top value=Green
D2 "EZA-EG3W11AV" 0603 1089.03,-2781.96 r0 bottom
D3 "EZA-EG3W11AV" 0603 944.91,-2782.38 r180 bottom
D4 "SZMM3Z5V6ST1G" SOD-323 355.77,-2742.24 r90 top value=5.6V
D5 "LG M67K-G1J2-24-Z" LG_M67K_Green 361.12,-1916.33 r270 top value=Green
D6 "LG M67K-G1J2-24-Z" LG_M67K_Green 358.9,-1576.87 r270 top value=Green
D7 "LG M67K-G1J2-24-Z" LG_M67K_Green 211.12,-1916.33 r270 top value=Green
D8 "LG M67K-G1J2-24-Z" LG_M67K_Green 208.12,-1576.33 r270 top value=Green
D9 "LG M67K-G1J2-24-Z" LG_M67K_Green 1775.47,-3483.92 r90 top value=Green
D10 "LG M67K-G1J2-24-Z" LG_M67K_Green 1883.02,-3484.49 r90 top value=Green
D11 "PMEG6020ER,115" SOD-123W 454.67,-3000.63 r0 top value=60V
D12 "PMEG6020ER,115" SOD-123W 1495.88,-1799.11 r270 top value=60V
D13 "LG M67K-G1J2-24-Z" LG_M67K_Green 1399.25,-2308.21 r180 top value=Green
D15 "LG M67K-G1J2-24-Z" LG_M67K_Green 1670.83,-3483.92 r90 top value=Green
FB1 "BLM18KG102SH1D" FP-BLM18-0_15-t0_8-IPC_C 1152.25,-2600.53 r180 bottom
H1 "NY PMS 440 0025 PH" "NY PMS 440 0025 PH"#1 337.76,-314.96 r0 top
H2 "NY PMS 440 0025 PH" "NY PMS 440 0025 PH"#1 1774.76,-314.96 r0 top
H13 "NY PMS 440 0025 PH" "NY PMS 440 0025 PH"#2 739.57,-1905.28 r0 top
J1 "2304372-1" TE_1PORT_B1-B 1014.47,-3531.62 r0 top
J2 "ERF8-050-01-L-D-EM2-TR" Samtec_ERF8-050-01-x-D-EM2 1056.73,4.1 r180 bottom locked
J3 "1714503106" Molex_1714503106 1051.73,-314.96 r0 bottom locked
J4 "61300111121" WURTH_61300111121 360.93,-1154.23 r180 top
J5 "TSW-103-07-G-S" TSW-103-07-X-S 281.12,-1726.33 r180 top
J6 "TSW-103-07-G-S" TSW-103-07-X-S 281.12,-1386.33 r180 top
J7 "TSW-105-07-G-S" TSW-105-07-X-S 1847.5,-531.05 r180 top
J8 "61300111121" WURTH_61300111121 1745.25,-629.91 r0 top
J9 "61300111121" WURTH_61300111121 1948.25,-631.91 r0 top
J11 "TSW-103-07-G-S" TSW-103-07-G-S 279.34,-585.09 r0 top
J12 "61300111121" WURTH_61300111121 758.98,-1494.51 r0 top
J13 "61300111121" WURTH_61300111121 758.21,-1647.91 r0 top
J14 "1935161" Phoenix_1935161 335,-3411.85 r0 top
J15 "TSW-102-07-G-S" TSW-102-07-G-S 156,-2990.11 r270 top
J16 "TSW-103-07-G-S" TSW-103-07-X-S 270.82,-831.09 r0 top
J17 "TSW-103-07-G-S" TSW-103-07-G-S 726.13,-2116.18 r0 top
J18 "TSW-101-07-G-S" TSW-101-07-G-S 1812.76,-2502.44 r90 top
J19 "61300111121" WURTH_61300111121 195.56,-1154.53 r0 top
J20 "TSW-103-07-G-S" TSW-103-07-G-S 1812.76,-2602.44 r0 top
J21 "TSW-103-07-G-S" TSW-103-07-G-S 1947.4,-1582.63 r0 top
J22 "TSW-103-07-G-S" TSW-103-07-G-S 1614.54,-2879.06 r270 top
J23 "TSW-101-07-G-S" TSW-101-07-G-S 1714.54,-2879.06 r180 top
L1 "BLM18AG102SN1D" 0603 1837.32,-1371.64 r90 top value="1000 ohm"
L2 "ADL32VHR-3R9M" FP-ADL32VHR-3R9M_SMT_3MM2_2MM5-MFG 1010.01,-2640.03 r0 bottom
L3 "BLM18AG102SN1D" 0603 731.41,-1063.27 r270 bottom value="1000 ohm"
L4 "BLM18AG102SN1D" 0603 938.59,-1710.47 r0 bottom value="1000 ohm"
L5 "ADM70S-2R6" FP-ADM70S-2R6_SMT_7MM0_6MM0-MFG 1009.35,-2569.87 r90 bottom
L6 "LQH32NH3R3J23L" FP-LQH32NH3R3J23L_1210.0-MFG 878.73,-2687.2 r180 bottom value=3.3uH
L7 "LQH32NH3R3J23L" FP-LQH32NH3R3J23L_1210.0-MFG 1131.4,-2687 r0 bottom value=3.3uH
L8 "ADF32T-800N" FP-ADF32T-800N_SMT_CMC_3MM2_2MM5-MFG 1015.09,-1953.1 r270 top
L9 "78438367100" FP-78438367100_SMT_IND_5MM4_5MM4-MFG 1331.4,-1768.31 r0 top value=10uH
L12 "PID77S-180M" FP-PID77S-180M_SMT4_7MM5_7MM5-MFG 1001.39,-2380.62 r270 bottom
LBL4 "THT-14-423-10" Label_650x200 1418.42,-3032.06 r90 bottom
Logo8 "WEEE logo" WEEE_Minimum 642.22,-3128.16 r180 bottom
Logo9 "CE Mark" CE_Mark_5mm 358.85,-3194.69 r180 bottom
Logo10 "Texas Instruments" TI_Stacked_Overlay_Small 1785.07,-2041.26 r270 bottom
Logo11 "FCC disclaimer" FCC_disclaimer -3512.93,307.98 r180 bottom
Q1 "BC847CLT1G" SOT-23 1891.2,-3449.66 r90 bottom value="45 V"
Q2 "MMBT3906" SOT-23 404.9,-2857.81 r90 top value="40 V"
Q3 "BC847CLT1G" SOT-23 1723.95,-3450.4 r90 bottom value="45 V"
Q5 "DMN10H220L-7" SOT-23 429.02,-2646.13 r180 top value=100V
R1 "CRCW08052K10FKEA" 0805_HV 1860.09,-3296.63 r90 bottom value=2.10k
R2 "CRCW06032K49FKEA" 0603 272.59,-739.93 r180 bottom value=2.49k
R3 "CRCW06032K49FKEA" 0603 1468.93,-740.72 r270 top value=2.49k
R4 "CRCW06032K49FKEA" 0603 1406.98,-740.98 r270 top value=2.49k
R5 "CRCW06032K49FKEA" 0603 1345.25,-741.25 r270 top value=2.49k
R6 "CRCW06032K49FKEA" 0603 1473.76,-1385.13 r180 bottom value=2.49k
R7 "CRCW040227R0JNED" 0402S 979.71,-1655.41 r180 top value=27
R8 "CRCW04020000Z0EDHP" 0402S 995.64,-1604.53 r270 top value=0
R9 "CRCW04020000Z0EDHP" 0402S 1035.44,-1604.53 r270 top value=0
R10 "CRCW040227R0JNED" 0402S 1050.9,-1655.41 r180 top value=27
R11 "CRCW08051K00FKEA" 0805_HV 1057.86,-2980.53 r90 bottom value=1.00k
R12 "CRCW08051K00FKEA" 0805_HV 970.68,-2980.53 r90 bottom value=1.00k
R13 "ERJ-8ENF1003V" 1206#2 950.2,-3185.77 r90 bottom value=100k
R14 "CRCW06032K49FKEA" 0603 1472.25,-1245.11 r180 bottom value=2.49k
R15 "RMCF0603ZT0R00" 0603 2014,-342.23 r90 bottom value=0
R16 "RK73Z1ETTP" 0402 1767.94,-1372.08 r270 top value=0
R18 "CRCW12061M00JNEA" 1206#2 800.75,-3522.03 r180 bottom value=1.0Meg
R19 "CRCW04022K20JNED" 0402 1628.87,-631.06 r180 bottom value=2.2k
R20 "RMCF0402FT10K0" 0402 1552.78,-822.15 r270 bottom value=10.0k
R21 "RMCF0402FT10K0" 0402 113.52,-561.04 r90 bottom value=10.0k
R22 "RMCF0603ZT0R00" 0603 1626.75,-799.82 r90 top value=0
R23 "CRCW04022K20JNED" 0402 496.92,-835.81 r270 bottom value=2.2k
R24 "CRCW06032K49FKEA" 0603 1473.34,-1446.62 r180 bottom value=2.49k
R25 "CRCW04022K49FKED" 0402 385.58,-1874.4 r0 bottom value=2.49k
R26 "CRCW04022K49FKED" 0402 381.7,-1536.11 r0 bottom value=2.49k
R27 "CRCW0402470RJNED" 0402 385.31,-1956.24 r0 bottom value=470
R28 "CRCW0402470RJNED" 0402 382.58,-1616.86 r0 bottom value=470
R29 "CRCW06034K53FKEA" 0603 1434.15,-1254.42 r180 top value=4.53k
R30 "CRCW0402100RFKED" 0402 770.17,-1180.83 r140 top value=100
R31 "CRCW06034K53FKEA" 0603 1433.79,-1145.38 r0 top value=4.53k
R32 "CRCW06032K49FKEA" 0603 307.7,-1037.78 r270 bottom value=2.49k
R33 "CRCW08052K10FKEA" 0805_HV 1752.9,-3296.05 r90 bottom value=2.10k
R34 "RK73Z1ETTP" 0402 2011.98,-1164.5 r0 top value=0
R35 "CRCW06032K49FKEA" 0603 1434.15,-1309.42 r180 top value=2.49k
R36 "CRCW04024K42FKED" 0402 1954.14,-1278.99 r0 top value=5.0k
R37 "CRCW04024K42FKED" 0402 1926.85,-1204.92 r270 top value=5.0k
R38 "3266W-1-502LF" TRIM_3266W 2017.2,-786.9 r270 top value="5 K"
R39 "RK73Z1ETTP" 0402S 980.32,-789.77 r270 top value=0
R40 "RK73Z1ETTP" 0402S 1019.02,-789.77 r270 top value=0
R41 "RMCF0402FT10K0" 0402 383.83,-733.96 r0 top value=10.0k
R42 "RT0603DRE0710KL" 0603 1772.43,-2805.04 r90 bottom value=10.0k
R43 "CRCW0402470RJNED" 0402 184.72,-1957.57 r0 bottom value=470
R44 "CRCW0402470RJNED" 0402 184.02,-1617.64 r0 bottom value=470
R45 "RK73Z1ETTP" 0402S 896.44,-791.74 r270 top value=0
R46 "RK73Z1ETTP" 0402S 855.56,-791.74 r270 top value=0
R47 "ERJ-2GEJ220X" 0402S 1201.66,-144.75 r270 top value=22
R48 "ERJ-2GEJ220X" 0402S 1163.04,-144.75 r270 top value=22
R49 "ERJ-2GEJ220X" 0402S 896.44,-791.74 r270 bottom value=22
R50 "ERJ-2GEJ220X" 0402S 855.56,-791.74 r270 bottom value=22
R51 "ERJ-2GEJ220X" 0402S 1009.46,-144.75 r270 top value=22
R52 "ERJ-2GEJ220X" 0402S 950.04,-144.75 r270 top value=22
R53 "ERJ-2GEJ220X" 0402S 910.69,-144.75 r270 top value=22
R54 "ERJ-2GEJ220X" 0402S 851.42,-144.75 r270 top value=22
R55 "ERJ-2GEJ220X" 0402S 792.85,-144.75 r270 top value=22
R56 "ERJ-2GEJ220X" 0402S 753.36,-144.75 r270 top value=22
R57 "ERJ-2GEJ220X" 0402S 1019.02,-789.77 r270 bottom value=22
R58 "ERJ-2GEJ220X" 0402S 980.32,-789.77 r270 bottom value=22
R59 "CRCW06032K49FKEA" 0603 1472.25,-1306.71 r180 bottom value=2.49k
R60 "RMCF0402FT10K0" 0402 184.06,-1037.13 r90 bottom value=10.0k
R61 "CRCW08055K10JNEA" 0805M 1567.65,-3424.86 r90 bottom value=5.1k
R62 "CRCW04020000Z0EDHP" 0402 1131.25,-1599.92 r0 bottom value=0
R63 "CRCW04022K20JNED" 0402 544.21,-835.81 r270 bottom value=2.2k
R64 "CRCW04022K20JNED" 0402 746.5,-773.55 r270 bottom value=2.2k
R65 "CRCW04022K20JNED" 0402 399.38,-461.01 r90 bottom value=2.2k
R66 "CRCW08051K00FKEA" 0805_HV 1648.55,-3296.05 r90 bottom value=1.00k
R67 "CRCW06032K49FKEA" 0603 1434.23,-1199.83 r180 top value=2.49k
R68 "CRCW04022K20JNED" 0402 1899.73,-3550.3 r0 bottom value=2.2k
R69 "CRCW04020000Z0EDHP" 0402 780.44,-1295.91 r230 top value=0
R70 "RMCF0402FT10K0" 0402 1823.87,-2806.7 r90 bottom value=10.0k
R71 "RMCF0603ZT0R00" 0603 1125.7,-1120.21 r0 bottom value=0
R72 "RMCF0603ZT0R00" 0603 690.31,-1419.98 r90 bottom value=0
R73 "RMCF0603ZT0R00" 0603 911.06,-1039.21 r90 bottom value=0
R74 "RMCF0603ZT0R00" 0603 1256.1,-1470.05 r90 bottom value=0
R75 "RK73Z1ETTP" 0402 1905.96,-1370.72 r270 top value=0
R76 "RC0603FR-073K3L" 0603 255.59,-2699.12 r0 top value=3.30k
R77 "RC0603FR-0768R1L" 0603 502.17,-2869.24 r90 top value=68.1
R78 "CRCW0402130KFKED" 0402 359.06,-2771.67 r270 bottom value=130k
R79 "RC0603FR-072K2L" 0603 255.5,-2753.78 r0 top value=2.20k
R80 "RT0402BRD0720KL" 0402 382.45,-2665.26 r180 bottom value=20.0k
R81 "RT0603DRE0710KL" 0603 255.69,-2644.83 r180 top value=10.0k
R82 "RT0603DRE07107KL" 0603 165.41,-2203.48 r90 top value=107k
R83 "RG1608P-913-B-T5" 0603 220.26,-2203.48 r90 top value=91.0k
R84 "RMCF0402FT10K0" 0402 640.26,-2495.14 r0 top value=10.0k
R85 "RMCF0402FT10K0" 0402 640.83,-2410.27 r0 top value=10.0k
R86 "RMCF0402FT10K0" 0402 110.55,-2427.1 r180 top value=10.0k
R87 "CRCW04020000Z0EDHP" 0402S 664.31,-2453.38 r180 top value=0
R88 "RT0603DRE0710KL" 0603 111.24,-2203.48 r270 top value=10.0k
R89 "RT0603DRE0710KL" 0603 274.53,-2203.48 r270 top value=10.0k
R90 "RMCF0402FT10K0" 0402S 169.4,-2414.01 r0 bottom value=10.0k
R91 "RMCF0402FT10K0" 0402S 116.82,-2059.93 r180 bottom value=10.0k
R92 "RMCF0402FT10K0" 0402S 116.82,-2020.93 r0 bottom value=10.0k
R93 "CRCW04022K20JNED" 0402 1738.73,-3551.6 r0 bottom value=2.2k
R95 "CRCW0603100KDHEAP" 0603S 1539.65,-1896.06 r90 bottom value=100k
R96 "3266W-1-503LF" TRIM_3266W 1337.4,-2170.01 r90 top value=50k
R97 "CRCW04024K70JNED" 0402S 1699.05,-841.27 r270 bottom value=4.7k
R98 "CRCW04024K70JNED" 0402S 1744.29,-841.27 r270 bottom value=4.7k
R99 "CRCW04020000Z0EDHP" 0402 648.83,-1250.29 r0 bottom value=0
R100 "CRCW04020000Z0EDHP" 0402 648.83,-1291.24 r0 bottom value=0
R101 "CRCW04022K49FKED" 0402S 1441.62,-1991.61 r180 top value=2.49k
R102 "CRCW04029K76FKED" 0402S 1299.83,-2101.7 r90 bottom value=9.76k
R103 "CRCW040236K0JNED" 0402S 1383.31,-2101.44 r90 bottom value=36k
R104 "RK73Z1ETTP" 0402S 1218.53,-2110.82 r270 bottom value=0
R105 "RK73Z1ETTP" 0402S 1178.88,-2110.82 r270 bottom value=0
R106 "RK73Z1ETTP" 0402S 1257.4,-2110.82 r90 bottom value=0
R107 "RK73Z1ETTP" 0402S 1139.58,-2110.82 r90 bottom value=0
R108 "ERJ-B2CFR05V" 0612 1216.56,-2477.58 r180 bottom value=0.05
R109 "RT0402BRD0720KL" 0402 1267.78,-2288.94 r180 top value=20.0k
R110 "RK73Z1ETTP" 0402 1999.13,-2750.64 r90 bottom value=0
R111 "CRCW0603270RJNEA" 0603S 2045.4,-2747.15 r270 bottom value=270
R112 "RC0402FR-074K99L" 0402S 1612.91,-2657.88 r90 bottom value=4.99k
R113 "RC0402FR-074K99L" 0402S 1553.62,-2580.51 r0 bottom value=4.99k
R114 "RC0402FR-074K99L" 0402S 1553.12,-2541.58 r0 bottom value=4.99k
R115 "ERJ-2RKF7152X" 0402S 1553.12,-2490.62 r0 bottom value=71.5k
R116 "RK73Z1ETTP" 0402S 1406.24,-1922.14 r0 bottom value=0
SH-J1 "SPC02SYAN" SPC02SYAN 331.12,-1725.08 r180 top value=1x2
SH-J2 "SPC02SYAN" SPC02SYAN 230.84,-1386.52 r180 top value=1x2
SH-J3 "SPC02SYAN" SPC02SYAN 319.53,-831.22 r180 top value=1x2
SH-J5 "SPC02SYAN" SPC02SYAN 229.34,-586.34 r180 top value=1x2
TP2 "TP_SM_1MM" TP_SM_1MM 1431.11,-1385.13 r180 top
TP3 "5127" Keystone5127 2024.09,-2026.12 r0 top
TP4 "5127" Keystone5127 1664.13,-1572.77 r180 top
TP5 "TP_SM_1MM" TP_SM_1MM 1429.63,-1450.46 r0 top
TP6 "TP_SM_1MM" TP_SM_1MM 1284.44,-1606.65 r90 top
TP8 "TP_SM_1MM" TP_SM_1MM 1103.27,-2472.29 r180 top
TP9 "TP_SM_1MM" TP_SM_1MM 1104.34,-2553.79 r180 top
TP10 "5127" Keystone5127 1924.22,-2293.78 r0 top
TP11 "TP_SM_1MM" TP_SM_1MM 1134.17,-2149.78 r90 top
TP13 "TP_SM_1MM" TP_SM_1MM 1450.43,-202.84 r90 top
TP24 "1502-2" Keystone1502-2 644.38,-859.77 r0 top
U1 "DP83TG720SWRNDRQ1" RND0036A 1045.58,-1252.86 r0 top
U2 "TPD2E2U06QDBZRQ1" DBZ0003A_N 1015.8,-1764.74 r90 top
U3 "TPS74501PQWDRBRQ1" DRB0008J 1969.45,-1044.94 r90 top
U4 "CAT24C256WI-GT3" SOIC-8 557.43,-627.42 r180 bottom
U5 "TLV76601QWDRBRQ1" DRB0008J-MFG 459.09,-2756.75 r0 bottom
U6 "OPA991QDBVRQ1" DBV0005A-MFG 278.27,-2959.77 r270 top
U7 "TLV6700DDCR" DDC0006A_N 191.76,-2334.28 r180 top
U8 "SN74AHC02QPWRQ1" PW0014A_N 432.16,-2403.15 r0 top
U9 "TCA6408AQPWRQ1" PW0016A-MFG 201.95,-2228.02 r270 bottom
U10 "LM5158QRTERQ1" RTE0016K-MFG 1338.81,-1955.97 r0 top
U11 "TLV4011QDCKRQ1" DCK0005A-MFG 1937.93,-2823.37 r90 bottom
U12 "INA237AQDGSRQ1" DGS0010A-MFG 1232.08,-2263.85 r270 bottom
U13 "TPS1HTC30AQPWPRQ1" PWP0014C-MFG 1451.34,-2568.4 r180 top
Y1 "ABM8AIG-25.000MHZ-12-2Z-T3" Abracon_ABM8AIG 696.77,-1253.79 r320 top
Y2 "CDC6CE02500CDLE" DLE0004A-MFG 696.77,-1253.79 r320 top

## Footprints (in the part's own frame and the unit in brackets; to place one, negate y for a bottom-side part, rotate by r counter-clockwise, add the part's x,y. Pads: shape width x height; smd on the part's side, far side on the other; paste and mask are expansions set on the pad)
0402 [mm] "0402 from SM-752 data"
  rect 0.8x0.6 smd: 1(-0.6,0) 2(0.6,0)
  silkscreen extent -1.22,-0.52 1.22,0.52, body extent -0.55,-0.3 0.55,0.3, height 0.6
0402S [mil] "Based on C0402S footprint from PADS legacy"
  rect 15x24 smd: 1(-20,0) 2(20,0)
  body extent -22,-12 22,12, height 24
0603 [mm] "0603 from SM-752 data"
  rect 1x0.95 smd: 1(-0.8,0) 2(0.8,0)
  silkscreen extent -1.52,-0.69 1.52,0.69, body extent -0.87,-0.47 0.87,0.47, height 1
0603S [mil]
  rect 20x35 smd: 1(-30,0) 2(30,0)
  body extent -34,-19 34,19, height 39
0612 [mm] "Panasonic recommended land pattern, fb97d03ed01.pdf dated April 2008"
  rect 0.95x3.2 smd: 1(-0.775,0) 2(0.775,0)
  silkscreen extent -1.1,-1.9 1.1,1.9, body extent -0.9,-1.7 0.9,1.7, height 0.85
0805_HV [mil] "0805 with 30mil clearance between pads"
  rect 50x63 smd: 1(-40,0) 2(40,0)
  silkscreen extent -74,-40 74,40, body extent -43,-29 43,29, height 57
0805_HV1 [mm] "Custom footprint based on analyzing multiple manufacturer recommendations"
  rrect10% 1x1.25 smd: 1(-1,0) 2(1,0)
  silkscreen extent -0.2,-0.75 0.2,0.75, body extent -1.1,-0.72 1.1,0.73, height 1.45
0805M [mm] "0805 from SM-752 data"
  rect 1.55x1.6 smd: 1(-0.975,0) 2(0.975,0)
  silkscreen extent -2.07,-1.12 2.07,1.12, body extent -1.1,-0.72 1.1,0.72, height 1.45
1206#1 [mm] "1206 from SM-752 data"
  rect 1.3x1.85 smd far side: 1(-1.45,0) 2(1.45,0)
  body extent -1.7,-0.9 1.7,0.9, height 1.35
1206#2 [mm] "1206 from SM-752 data"
  rect 1.3x1.85 smd: 1(-1.45,0) 2(1.45,0)
  silkscreen extent -2.4,-1.21 2.4,1.21, body extent -1.7,-0.9 1.7,0.9, height 1.35
1210_220 [mm] "1210"
  rect 1.3x2.7 smd: 1(-1.45,0) 2(1.45,0)
  silkscreen extent -2.32,-1.57 2.32,1.57, body extent -1.7,-1.35 1.7,1.35, height 2.2
Abracon_ABM8AIG [mm] "SMD, 4-Leads, Body 3.2x2.5mm"
  rrect9% 1.1x1.3 smd: 1(-0.95,1.15) 2(-0.95,-1.15) 3(0.95,-1.15) 4(0.95,1.15)
  silkscreen extent -1.8,1.3 -1.28,2.07, body extent -1.3,-1.65 1.3,1.65, height 0.8
CE_Mark_5mm [mil] "Minimum text height for CE Mark"
  silkscreen extent -138,-98 138,98
DBV0005A-MFG [mm]
  rrect17% 1.1x0.6 smd paste+0 mask+0: 1(-1.3,0.95) 2(-1.3,0) 3(-1.3,-0.95) 4(1.3,-0.95) 5(1.3,0.95)
  silkscreen extent -2.57,-1.53 0.87,1.53, body extent -1.95,-1.78 1.95,1.78, height 0.25
DBZ0003A_N [mm] "SOT23, 3-Leads, Body 2.9x1.3mm, Pitch 0.95mm, Lead Span 2.4mm, IPC Medium Density"
  rrect17% 1x0.6 smd: 1(-1.2,0.95) 2(-1.2,-0.95) 3(1.2,0)
  silkscreen extent 0.2,-1.5 0.7,1.5, body extent -1.26,-1.46 1.26,1.46, height 0.98
DCK0005A-MFG [mm]
  rrect25% 0.95x0.4 smd paste+0 mask+0: 1(-1.1,0.65) 2(-1.1,0) 3(-1.1,-0.65) 4(1.1,-0.65) 5(1.1,0.65)
  silkscreen extent -2.25,-1.07 0.23,1.07, body extent -1.05,-1 1.05,1, height 1.1
DDC0006A_N [mm]
  rrect17% 1x0.6 smd: 1(-1.375,0.95) 2(-1.375,0) 3(-1.375,-0.95) 4(1.375,-0.95) 5(1.375,0) 6(1.375,0.95)
  silkscreen extent -1.75,-1.52 0.7,1.53, body extent -1.43,-1.48 1.43,1.49, height 0.92
DGS0010A-MFG [mm]
  rrect33% 1.45x0.3 smd paste+0 mask+0: 1(-2.2,1) 2(-2.2,0.5) 3(-2.2,0) 4(-2.2,-0.5) 5(-2.2,-1) 6(2.2,-1) 7(2.2,-0.5) 8(2.2,0) 9(2.2,0.5) 10(2.2,1)
  silkscreen extent -1.93,-1.55 1.05,2.07, body extent -2.45,-1.5 2.45,1.5, height 1.1
DLE0004A-MFG [mm]
  rrect17% 0.6x0.7 smd paste-1000 mask+0: 1(-0.8,1.05) 2(-0.8,-1.05) 3(0.8,-1.05) 4(0.8,1.05)
  silkscreen extent -1.9,-1.65 1.3,1.65, body extent -1.4,-1.75 1.4,1.75, height 0.25
DRB0008J [mm] "VSON-8"
  rrect33% 0.6x0.31 smd: 1(-1.4,0.975) 2(-1.4,0.325) 3(-1.4,-0.325) 4(-1.4,-0.975) 5(1.4,-0.975) 6(1.4,-0.325) 7(1.4,0.325) 8(1.4,0.975)
  rrect6% 1.65x2.4 smd paste-1.2: 9(0,0)
  silkscreen extent -1.73,-1.73 1.73,1.73, body extent -1.55,-1.55 1.55,1.55, height 1.01
DRB0008J-MFG [mm]
  rrect32% 0.6x0.31 smd paste+0 mask+0: 1(-1.4,0.975) 2(-1.4,0.325) 3(-1.4,-0.325) 4(-1.4,-0.975) 5(1.4,-0.975) 6(1.4,-0.325) 7(1.4,0.325) 8(1.4,0.975)
  rrect6% 1.65x2.4 smd paste-1000 mask+0: 9(0,0)
  silkscreen extent -1.76,-1.55 1.55,1.81, body extent -1.5,-1.5 1.5,1.5, height 1
FCC_disclaimer [mil]
FP-78438367100_SMT_IND_5MM4_5MM4-MFG [mm]
  rrect6% 1.7x5.6 smd paste+0 mask+0: 1(-1.95,0) 2(1.95,0)
  silkscreen extent -2.72,-2.8 0.72,3.29, body extent -2.9,-2.9 2.9,2.9, height 0.25
FP-ADF32T-800N_SMT_CMC_3MM2_2MM5-MFG [mm]
  rrect9% 1.2x1.15 smd paste+0 mask+0: 1(-1.45,0.775) 2(-1.45,-0.775) 3(1.45,-0.775) 4(1.45,0.775)
  silkscreen extent -2.72,-1.45 0.48,1.45, body extent -2.15,-1.55 2.15,1.55, height 0.25
FP-ADL32VHR-3R9M_SMT_3MM2_2MM5-MFG [mm]
  rrect9% 1.2x1.15 smd paste+0 mask+0: 1(-1.45,0.775) 2(-1.45,-0.775) 3(1.45,-0.775) 4(1.45,0.775)
  silkscreen extent -3.12,-1.45 2.18,1.45, body extent -1.95,-1.25 1.95,1.25, height 2.5
FP-ADM70S-2R6_SMT_7MM0_6MM0-MFG [mm]
  rrect7% 2.5x1.5 smd paste+0 mask+0: 1(-3.25,1.5) 2(-3.25,-1.5) 3(3.25,-1.5) 4(3.25,1.5)
  silkscreen extent -4.65,-3.1 3.6,3.1, body extent -3.5,-3 3.5,3, height 3.5
FP-BLM18-0_15-t0_8-IPC_C [mil]
  rect 35.67x33.79 smd paste+0 mask+0: 1(-22.68,0) 2(22.68,0)
  silkscreen extent -41,-34 41,34, body extent -31,-16 31,16, height 37
FP-C0603C225M8PAC7867_0603-MFG [mm]
  rrect13% 0.75x0.9 smd paste+0 mask+0: 1(-0.6,0) 2(0.6,0)
  silkscreen extent -0.87,-0.82 0.87,0.82, body extent -0.8,-0.4 0.8,0.4, height 0.9
FP-C1210C472KGRAC7800_1210-MFG [mm]
  rrect11% 0.95x2.6 smd paste+0 mask+0: 1(-1.4,0) 2(1.4,0)
  silkscreen extent -0.55,-1.35 0.55,1.35, body extent -1.6,-1.25 1.6,1.25, height 2.3
FP-LQH32NH3R3J23L_1210.0-MFG [mil]
  round 39.16 smd paste+0 mask+0: 1(-51.67,-2.46)
  round 39.86 smd paste+0 mask+0: 2(47.74,2.46)
  Top Layer region: 25.59,-39.37 25.59,39.37 64.96,39.37 64.96,19.68 108.27,19.68 108.27,-19.69 64.96,-19.69 64.96,-39.37
  Top Layer region: -64.96,-39.37 -64.96,-19.69 -108.27,-19.69 -108.27,19.68 -64.96,19.68 -64.96,39.37 -25.59,39.37 -25.59,-39.37
  silkscreen extent -11,-53 11,53, body extent -63,-49 63,49, height 87
FP-PID77S-180M_SMT4_7MM5_7MM5-MFG [mm]
  rrect9% 1.1x2.1 smd paste+0 mask+0: 1(-0.85,-2.7) 2(0.85,-2.7) 3(0.85,2.7) 4(-0.85,2.7)
  silkscreen extent -3.75,-4.43 3.75,3.75, body extent -3.75,-3.75 3.75,3.75, height 7.5
Keystone1502-2 [mm] "Double Turret"
  round 3.5 hole 2.5: 1(0,0)
  silkscreen extent -2.3,-2.3 2.3,2.3, body extent -1.6,-1.6 1.59,1.6, height 5.62
Keystone5127 [mil] "Keystone Multipurpose loops"
  round 87 hole 63: 1(0,0)
  silkscreen extent -70,-70 70,70, body extent -63,-63 63,62, height 319
Label_650x200 [mil] "Thermal Transfer Label"
  round 1 on Mech14: 0(0,0)
  silkscreen extent -325,-100 325,100, body extent -325,-100 325,100, height 1
LG_M67K_Green [mm] "SMD, 2-Leads, Body 2x1.4mm, Pitch 2mm"
  rect 0.8x1 smd mask+0: 1(-1,0) 2(1,0)
  silkscreen extent -2.1,-1 1.05,1, body extent -1.05,-0.75 1.05,0.75, height 1.4
Molex_1714503106 [mm] "Receptacle, 0.8mm, 30x2, SMT"
  rrect22% 0.45x1.1 smd: 1(-11.6,3.03) 2(-10.8,3.03) 3(-10,3.03) 4(-9.2,3.03) 5(-8.4,3.03) 6(-7.6,3.03) 7(-6.8,3.03) 8(-6,3.03) 9(-5.2,3.03) 10(-4.4,3.03) 11(-3.6,3.03) 12(-2.8,3.03) 13(-2,3.03) 14(-1.2,3.03) 15(-0.4,3.03) 16(0.4,3.03) 17(1.2,3.03) 18(2,3.03) 19(2.8,3.03) 20(3.6,3.03) 21(4.4,3.03) 22(5.2,3.03) 23(6,3.03) 24(6.8,3.03) 25(7.6,3.03) 26(8.4,3.03) 27(9.2,3.03) 28(10,3.03) 29(10.8,3.03) 30(11.6,3.03) 31(-11.6,-3.03) 32(-10.8,-3.03) 33(-10,-3.03) 34(-9.2,-3.03) 35(-8.4,-3.03) 36(-7.6,-3.03) 37(-6.8,-3.03) 38(-6,-3.03) 39(-5.2,-3.03) 40(-4.4,-3.03) 41(-3.6,-3.03) 42(-2.8,-3.03) 43(-2,-3.03) 44(-1.2,-3.03) 45(-0.4,-3.03) 46(0.4,-3.03) 47(1.2,-3.03) 48(2,-3.03) 49(2.8,-3.03) 50(3.6,-3.03) 51(4.4,-3.03) 52(5.2,-3.03) 53(6,-3.03) 54(6.8,-3.03) 55(7.6,-3.03) 56(8.4,-3.03) 57(9.2,-3.03) 58(10,-3.03) 59(10.8,-3.03) 60(11.6,-3.03)
  round 0.75 hole 1.05 unplated mask+0.102: ALIGN1(-13.55,-1.98) ALIGN2(13.55,1.98)
  round 1.35 hole 1: MH1(-13.8,0) MH2(13.8,0)
  body extent -14.4,-3.43 14.4,3.43, height 4.55
"NY PMS 440 0025 PH"#1 [mm] "4-40 nylon screw and mounting hole"
  round 3 hole 3.2: 1(0,0)
  body extent -3.3,-3.3 3.3,3.3, height 2.69
"NY PMS 440 0025 PH"#2 [mm] "4-40 nylon screw and mounting hole"
  round 0 hole 3.2: 1(0,0)
  body extent -3.3,-3.3 3.3,3.3, height 2.69
Phoenix_1935161 [mm] "TH, 2-Leads, Body 10x9mm, Pitch 5mm"
  rect 1.8x1.8 hole 1.3: 1(-2.5,0)
  round 1.8 hole 1.3: 2(2.5,0)
  silkscreen extent -5.5,-5 5.57,4, body extent -5,-5 5.57,4, height 11.4
PW0014A_N [mm] "TSOP, 14-Leads, Body 5x4.4mm, Pitch 0.65mm, IPC Medium Density"
  oval 1.4x0.45 smd: 1(-2.95,1.95) 2(-2.95,1.3) 3(-2.95,0.65) 4(-2.95,0) 5(-2.95,-0.65) 6(-2.95,-1.3) 7(-2.95,-1.95) 8(2.95,-1.95) 9(2.95,-1.3) 10(2.95,-0.65) 11(2.95,0) 12(2.95,0.65) 13(2.95,1.3) 14(2.95,1.95)
  silkscreen extent -3.4,-2.55 1.85,2.55, body extent -3.21,-2.5 3.21,2.5, height 1
PW0016A-MFG [mm]
  rrect22% 1.5x0.45 smd paste+0 mask+0: 1(-2.9,2.275) 2(-2.9,1.625) 3(-2.9,0.975) 4(-2.9,0.325) 5(-2.9,-0.325) 6(-2.9,-0.975) 7(-2.9,-1.625) 8(-2.9,-2.275) 9(2.9,-2.275) 10(2.9,-1.625) 11(2.9,-0.975) 12(2.9,-0.325) 13(2.9,0.325) 14(2.9,0.975) 15(2.9,1.625) 16(2.9,2.275)
  silkscreen extent -2.51,-2.55 1.78,3.14, body extent -3.2,-2.5 3.2,2.5, height 1.2
PWP0014C-MFG [mm]
  rrect33% 1.6x0.3 smd paste-1000 mask+0: 1(-2.8,1.95) 2(-2.8,1.3) 3(-2.8,0.65) 4(-2.8,0) 5(-2.8,-0.65) 6(-2.8,-1.3) 7(-2.8,-1.95) 8(2.8,-1.95) 9(2.8,-1.3) 10(2.8,-0.65) 11(2.8,0) 12(2.8,0.65) 13(2.8,1.3) 14(2.8,1.95)
  rrect3% 3.4x5 smd paste-1000 mask-1000: 15(0,0)
  silkscreen extent -4.28,-2.7 2.4,2.7, body extent -3.7,-2.8 3.7,2.8, height 0.25
RND0036A [mm] "TI"
  oval 0.6x0.25 smd: 1(-2.9,2) 2(-2.9,1.5) 3(-2.9,1) 4(-2.9,0.5) 5(-2.9,0) 6(-2.9,-0.5) 7(-2.9,-1) 8(-2.9,-1.5) 9(-2.9,-2) 19(2.9,-2) 20(2.9,-1.5) 21(2.9,-1) 22(2.9,-0.5) 23(2.9,0) 24(2.9,0.5) 25(2.9,1) 26(2.9,1.5) 27(2.9,2)
  oval 0.25x0.6 smd: 10(-2,-2.9) 11(-1.5,-2.9) 12(-1,-2.9) 13(-0.5,-2.9) 14(0,-2.9) 15(0.5,-2.9) 16(1,-2.9) 17(1.5,-2.9) 18(2,-2.9) 28(2,2.9) 29(1.5,2.9) 30(1,2.9) 31(0.5,2.9) 32(0,2.9) 33(-0.5,2.9) 34(-1,2.9) 35(-1.5,2.9) 36(-2,2.9)
  rect 3.7x3.7 smd paste-1.85: 37(0,0)
  silkscreen extent -3.17,-3.17 3.17,3.2, body extent -3,-3 3,3, height 0.81
RTE0016K-MFG [mm]
  rrect42% 0.6x0.24 smd paste+0 mask+0: 1(-1.4,0.75) 2(-1.4,0.25) 3(-1.4,-0.25) 4(-1.4,-0.75) 9(1.4,-0.75) 10(1.4,-0.25) 11(1.4,0.25) 12(1.4,0.75)
  rrect42% 0.24x0.6 smd paste+0 mask+0: 5(-0.75,-1.4) 6(-0.25,-1.4) 7(0.25,-1.4) 8(0.75,-1.4) 13(0.75,1.4) 14(0.25,1.4) 15(-0.25,1.4) 16(-0.75,1.4)
  rrect6% 1.66x1.66 smd paste-1000 mask+0: 17(0,0)
  silkscreen extent -1.96,-1.58 1.58,1.9, body extent -1.8,-1.8 1.8,1.8, height 0.25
